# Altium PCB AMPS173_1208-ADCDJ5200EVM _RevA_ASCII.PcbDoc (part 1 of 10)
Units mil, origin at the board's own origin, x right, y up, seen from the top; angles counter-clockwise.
Board outline 10500 x 2750 mil, 14 copper layers (Top Copper, Layer 2 (GND1), Layer 3 (SIG1), Layer 4 (GND2, Layer 5 (PWR1), Layer 6 (GND3), Layer 7 (PWR/SIGNAL2), Layer 8 (PWR/SIGNAL3), Layer 9 (GND4), Layer 10 PWR2), Layer 11 (GND5), Layer 12 (SIG4), Layer 13 (GND6), Bottom Copper), stack 60.6 mil thick; 701 components, 826 nets, 3386 pads, 2128 vias.
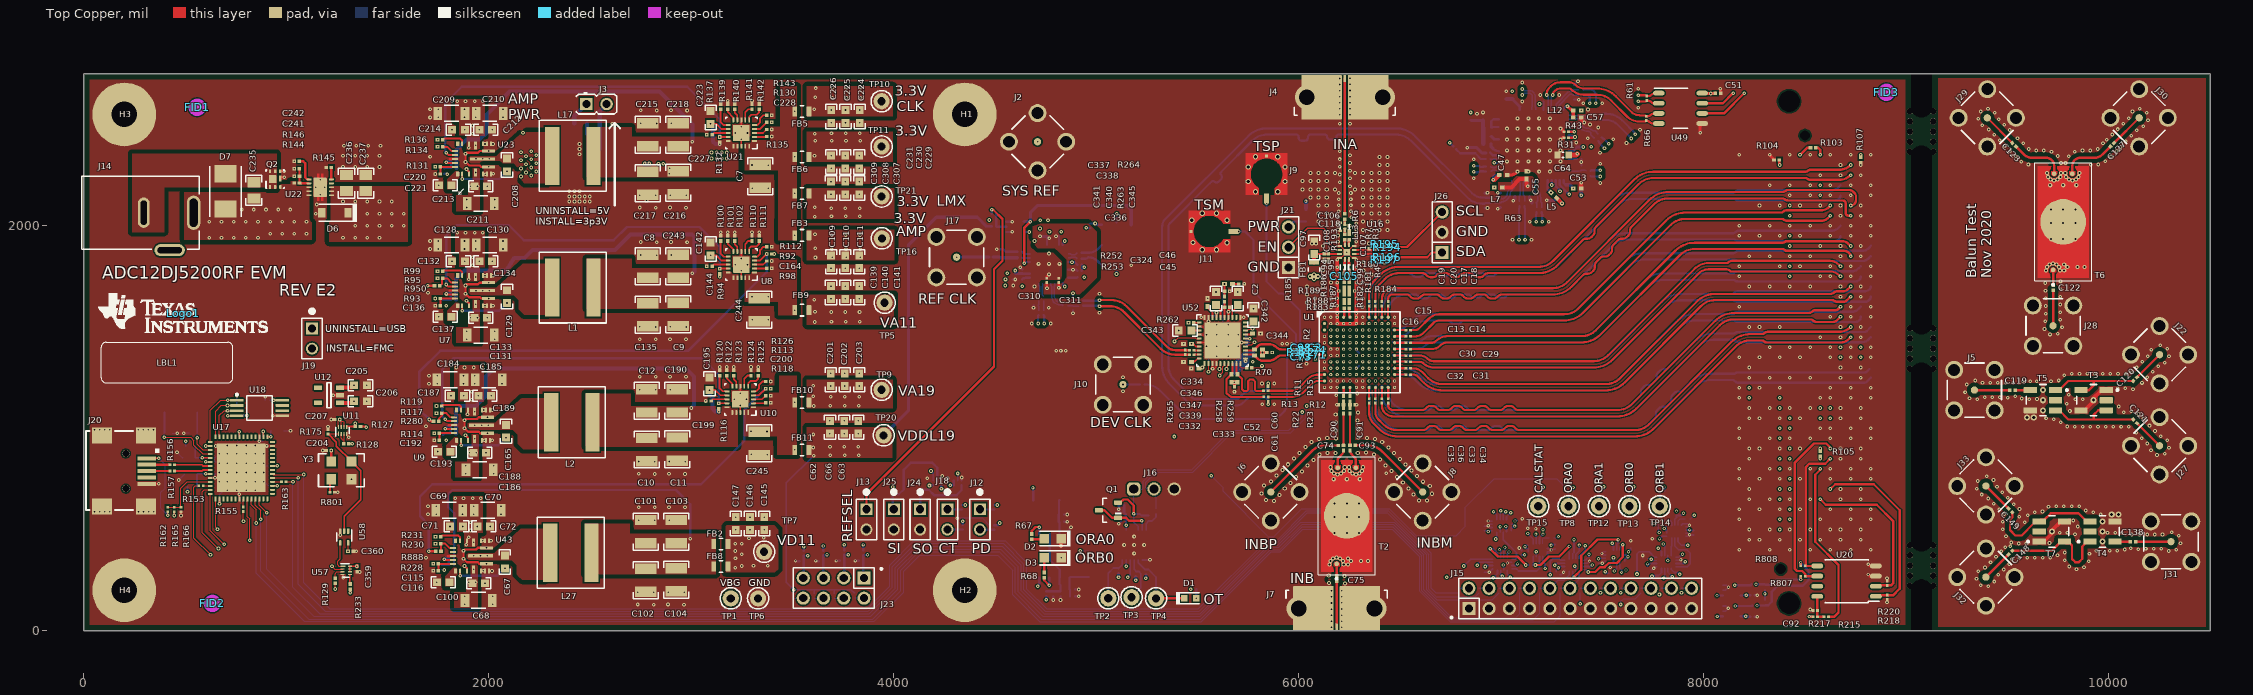
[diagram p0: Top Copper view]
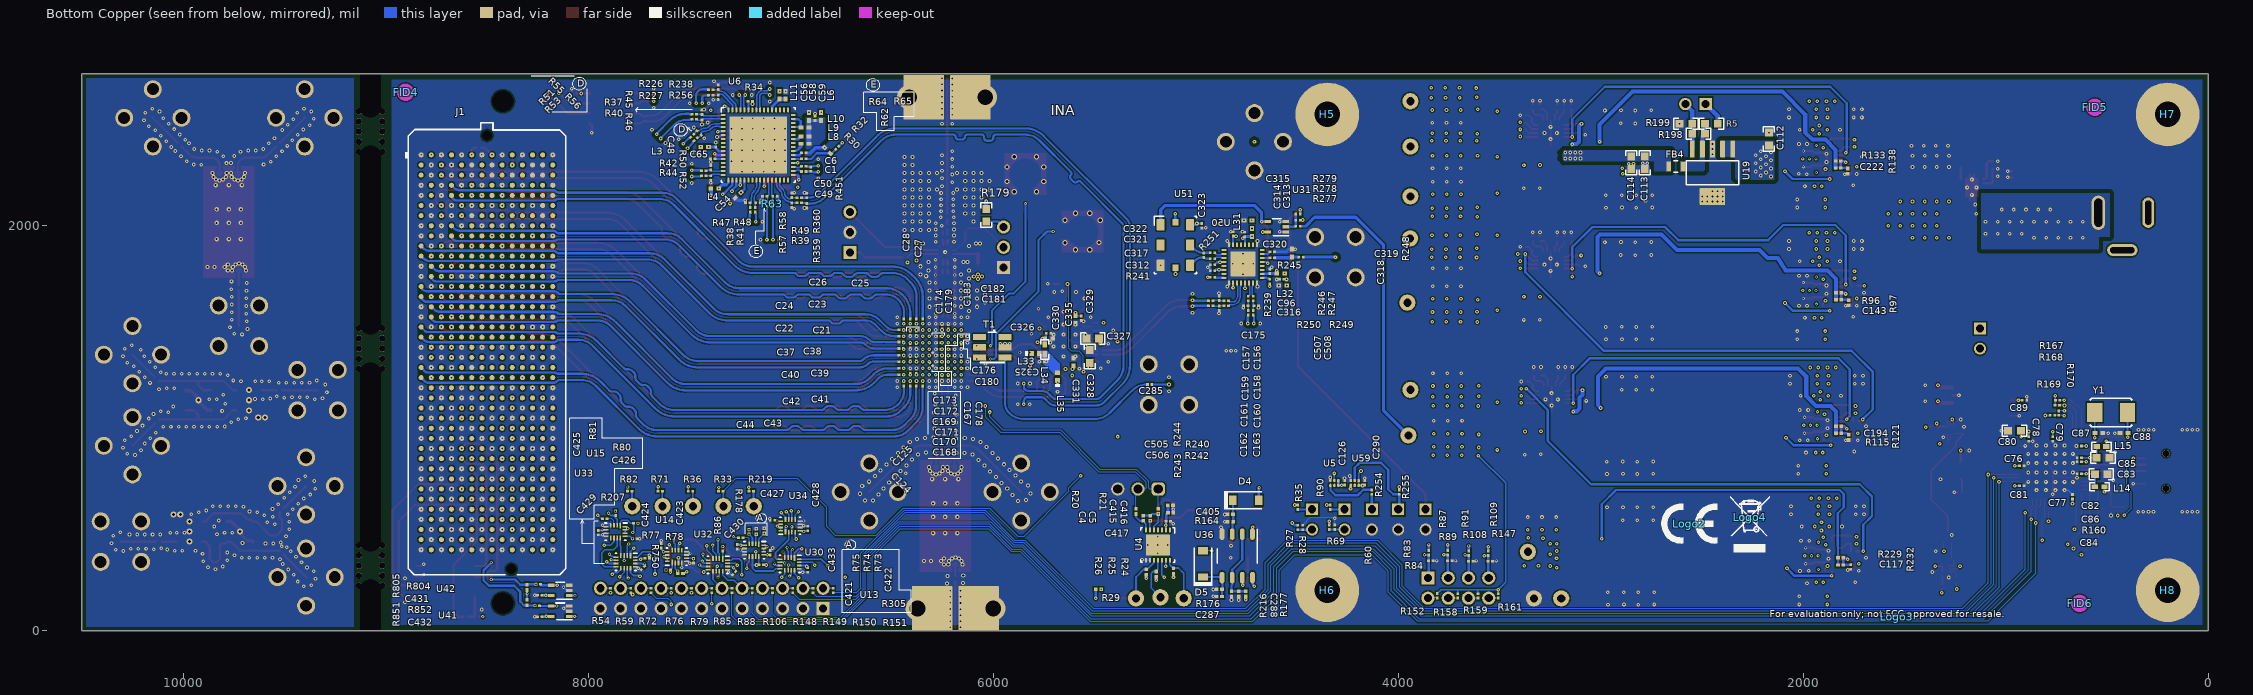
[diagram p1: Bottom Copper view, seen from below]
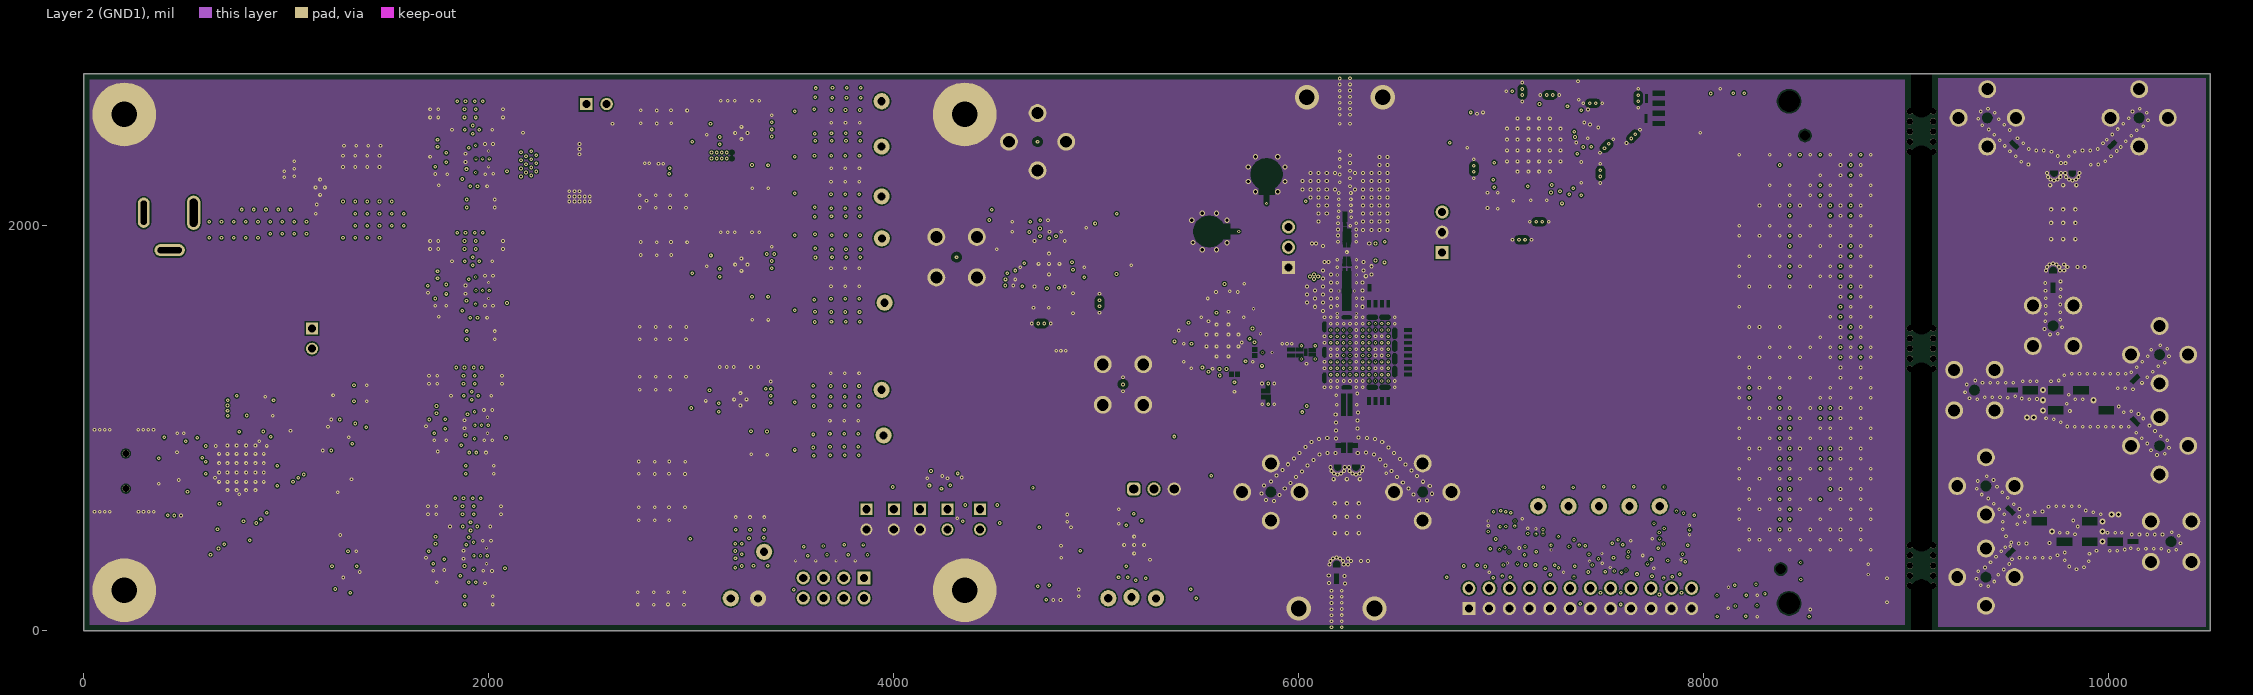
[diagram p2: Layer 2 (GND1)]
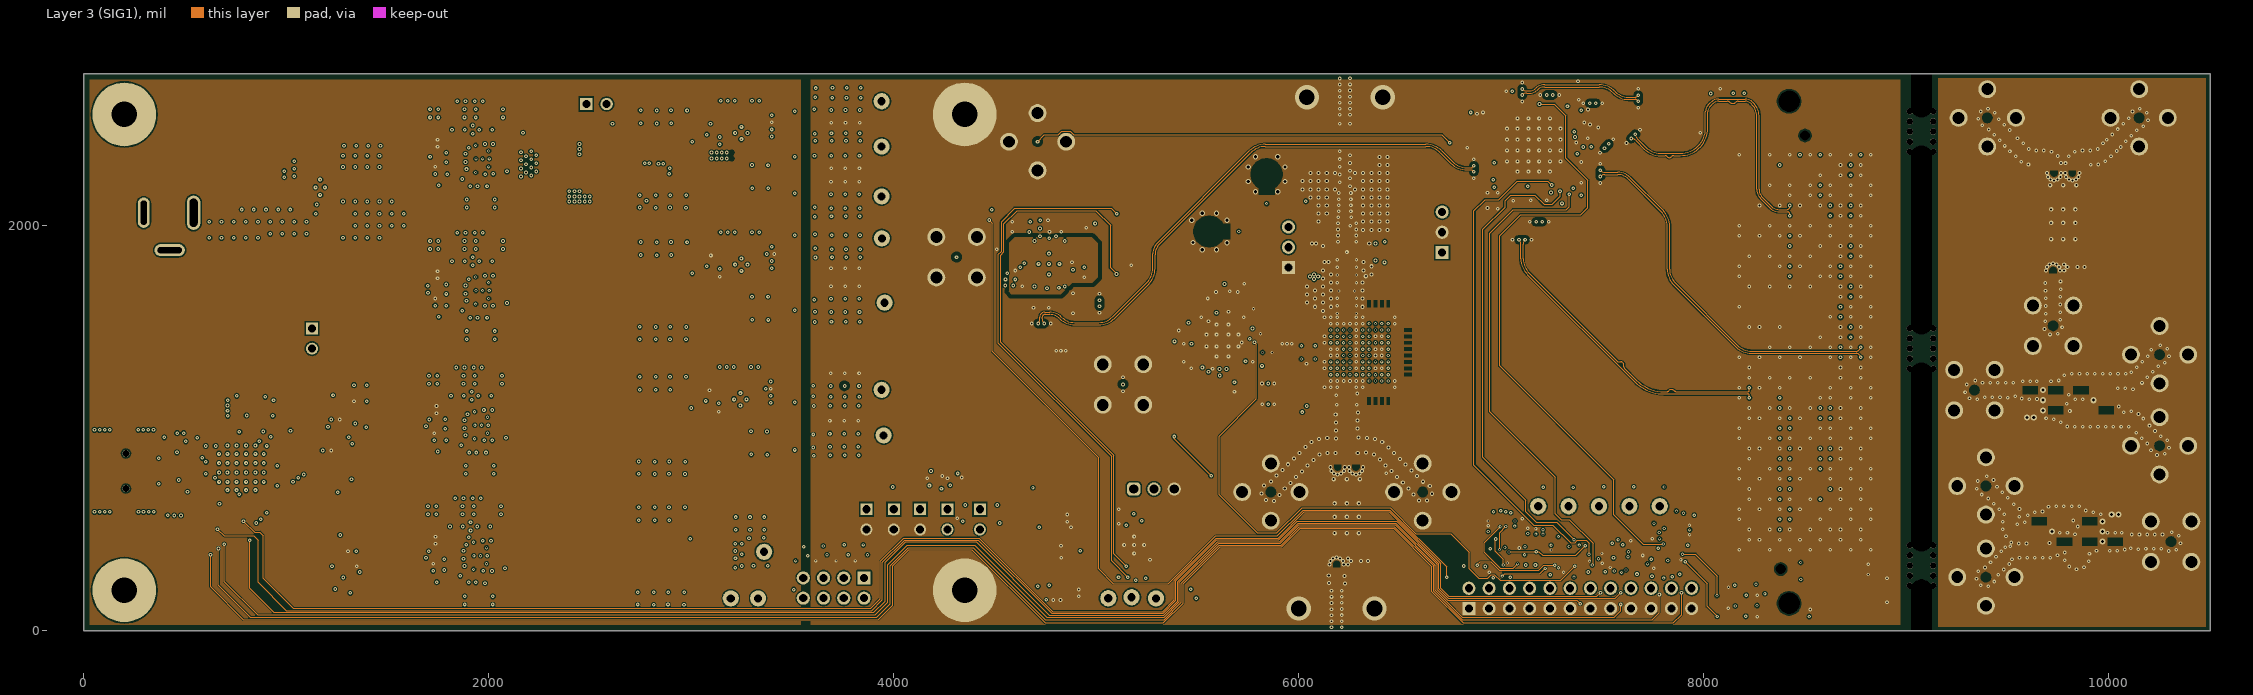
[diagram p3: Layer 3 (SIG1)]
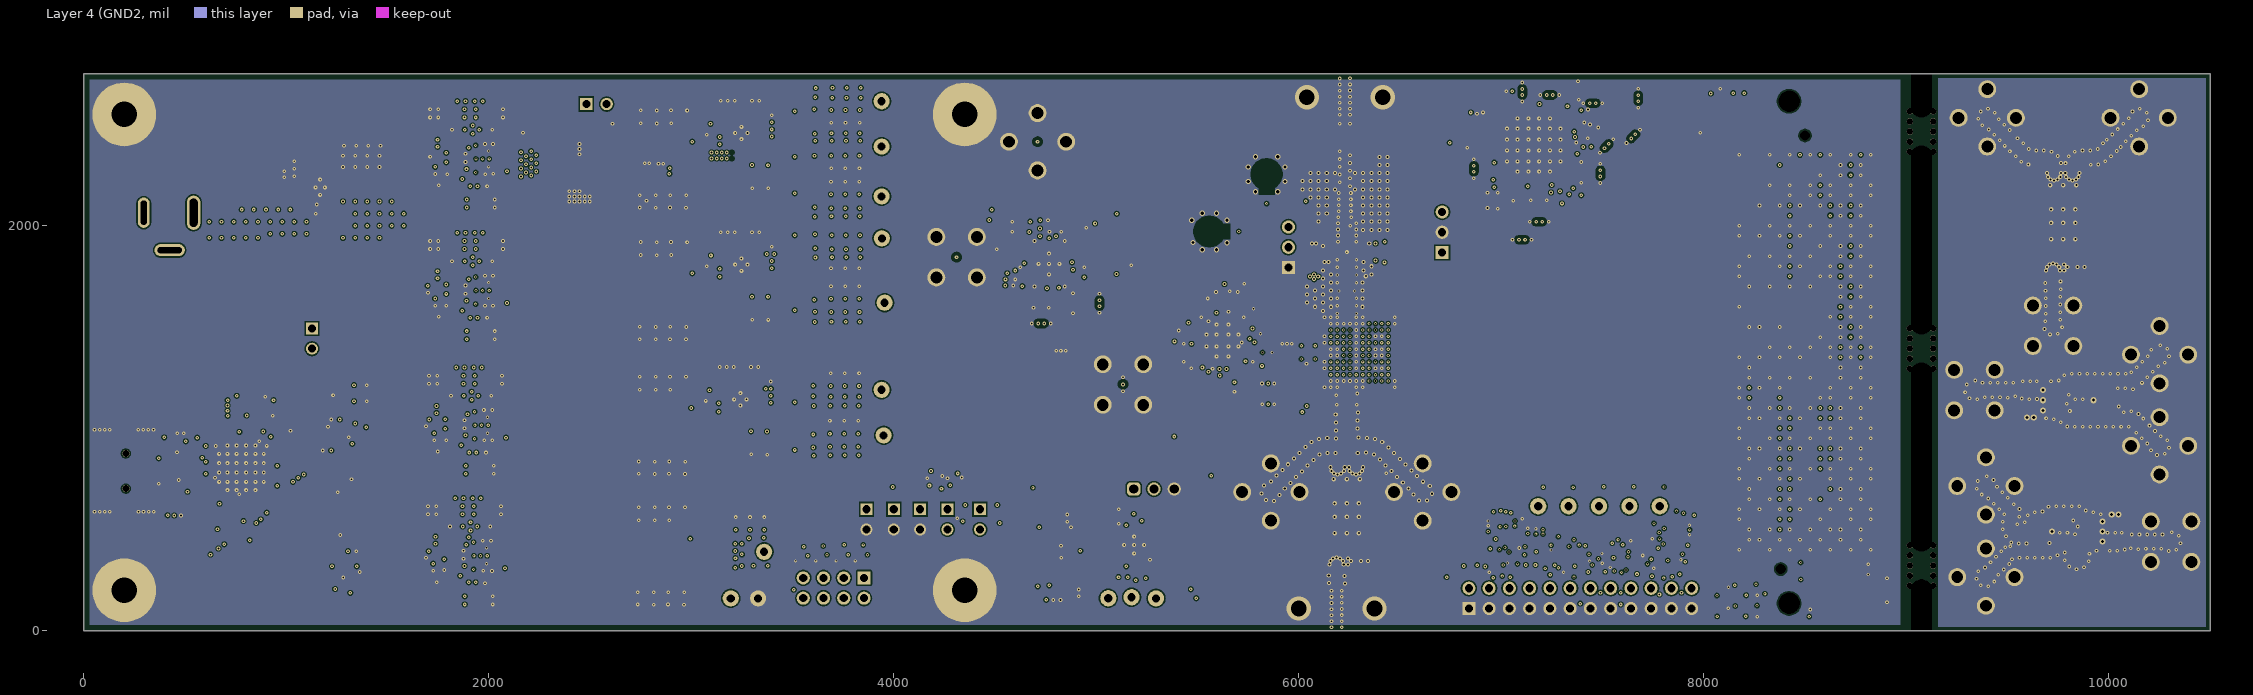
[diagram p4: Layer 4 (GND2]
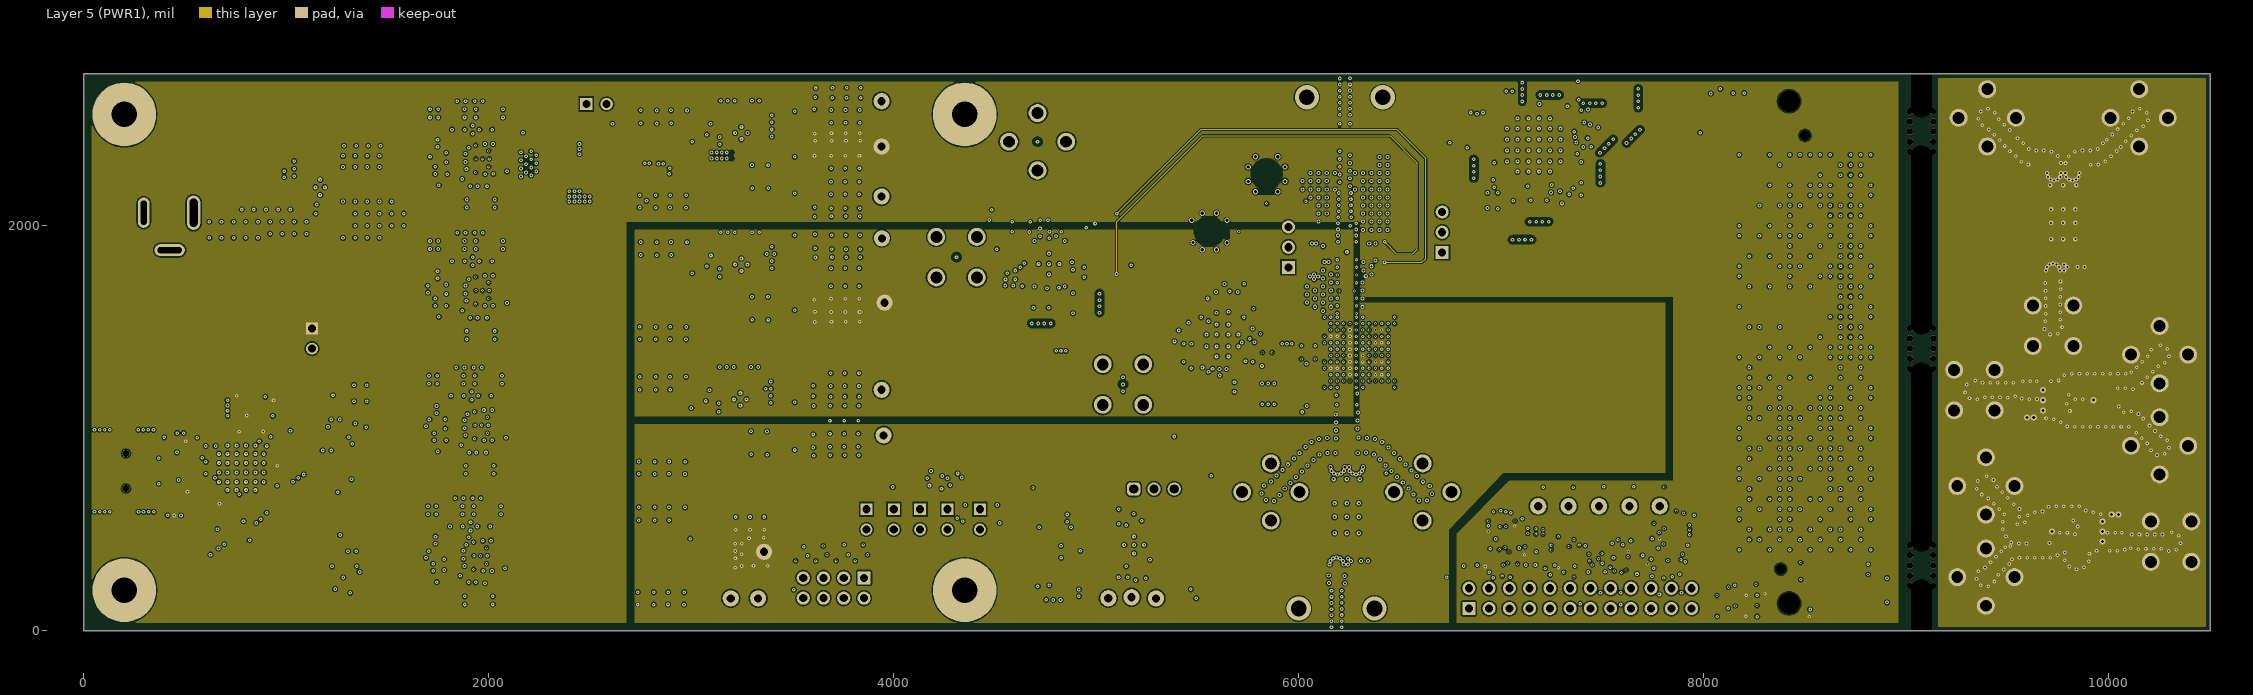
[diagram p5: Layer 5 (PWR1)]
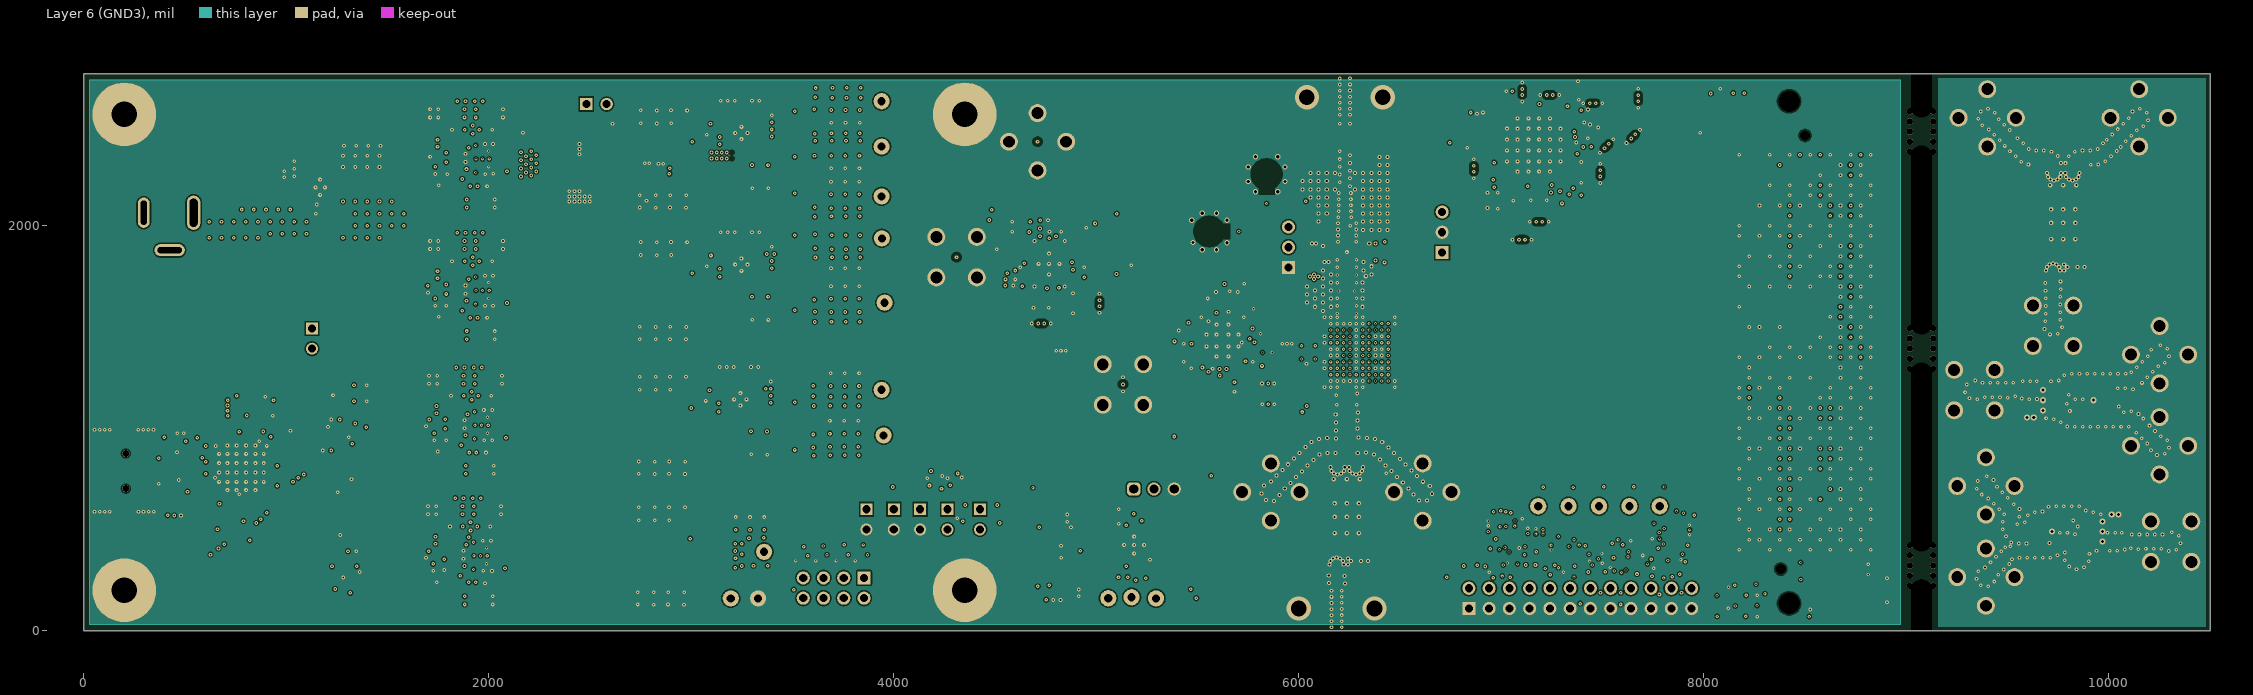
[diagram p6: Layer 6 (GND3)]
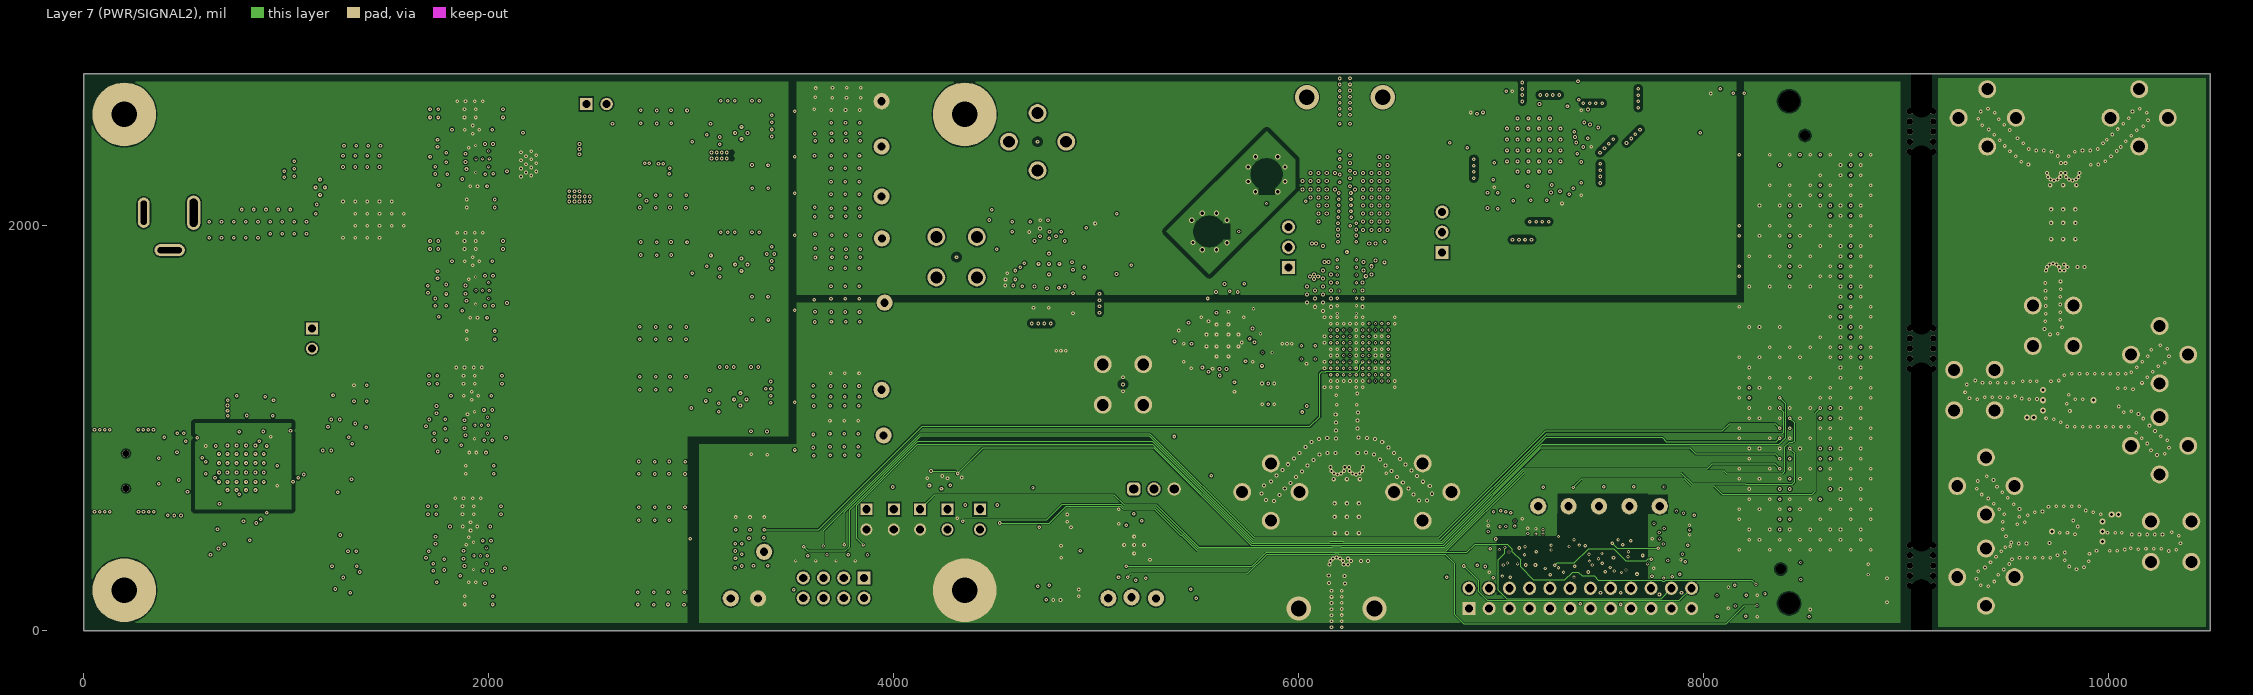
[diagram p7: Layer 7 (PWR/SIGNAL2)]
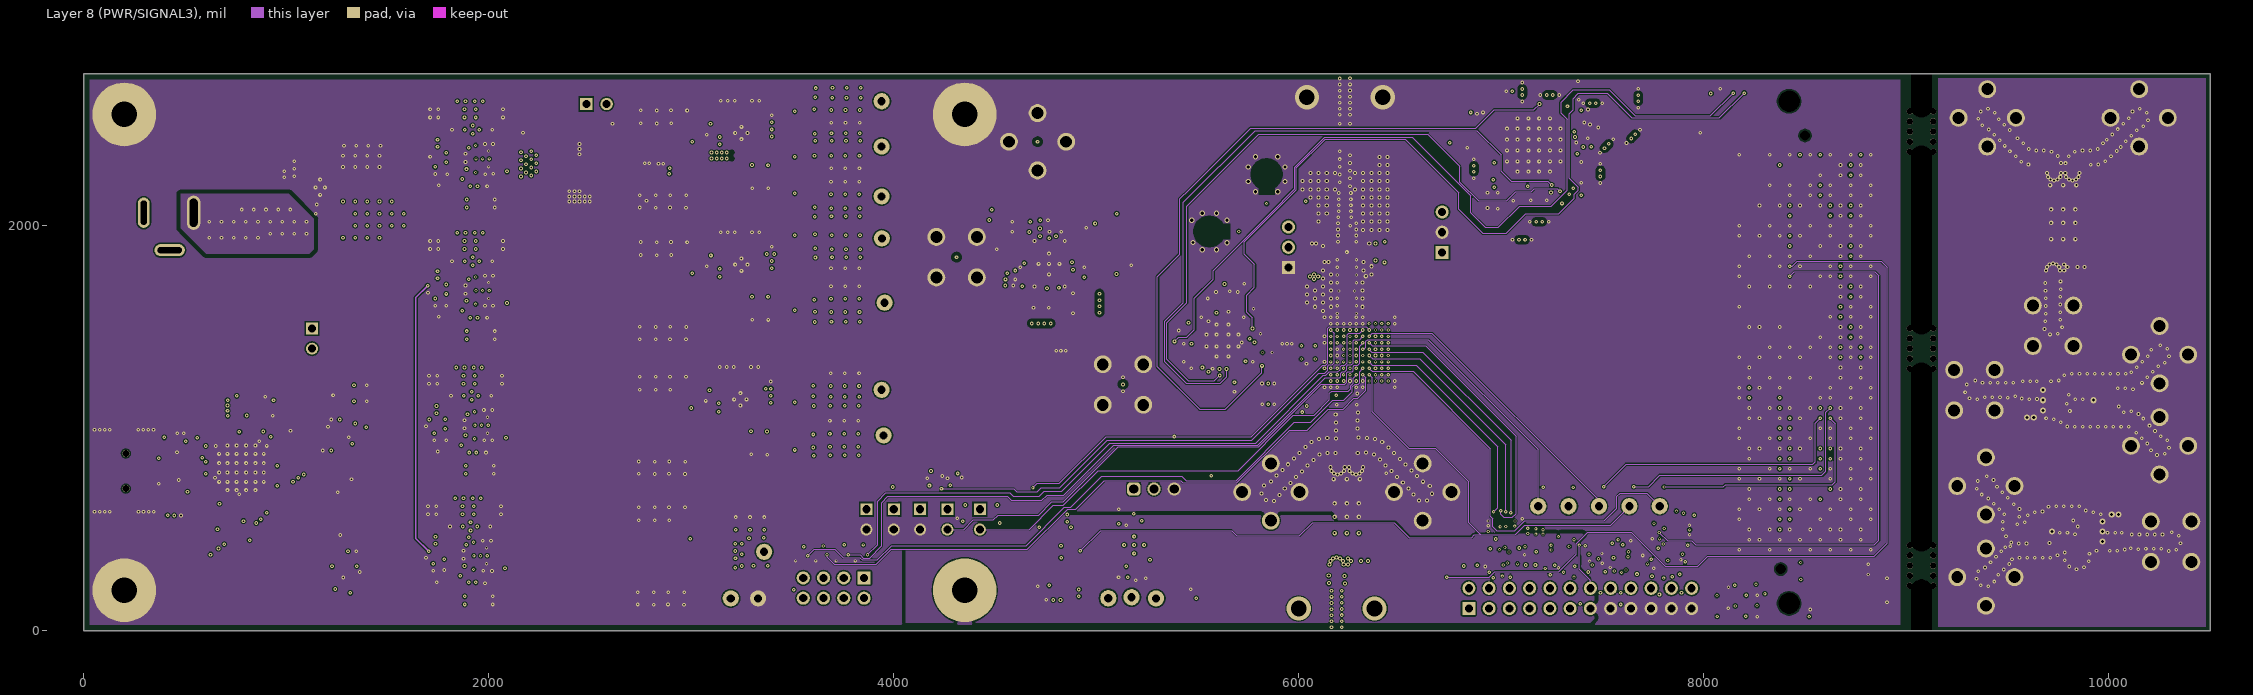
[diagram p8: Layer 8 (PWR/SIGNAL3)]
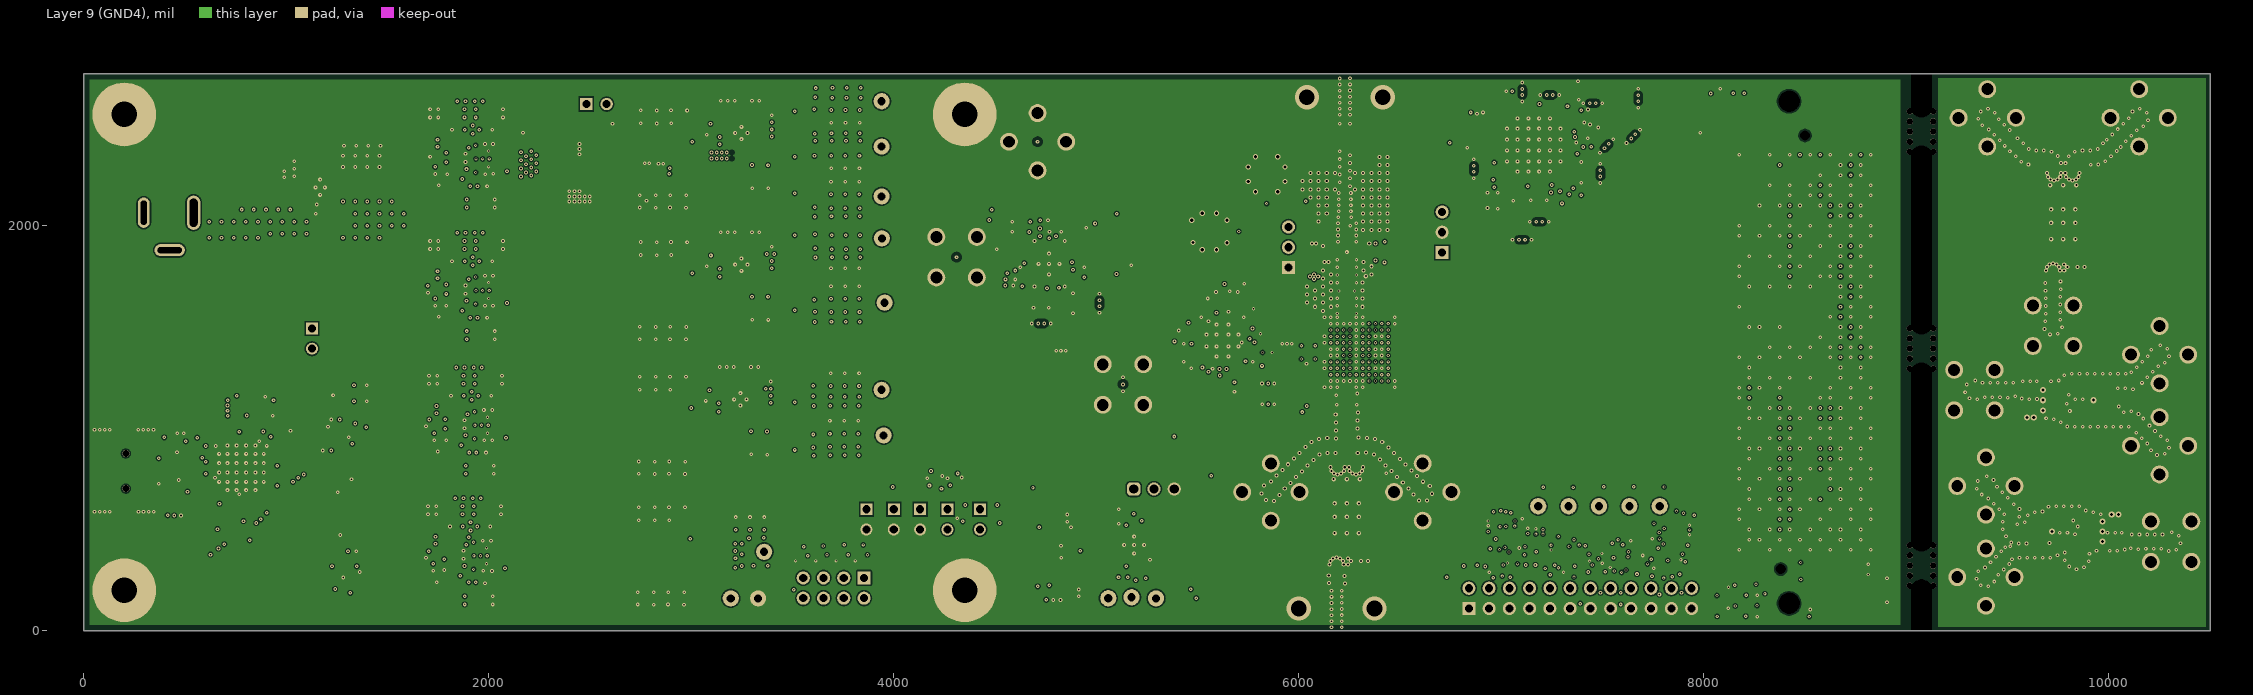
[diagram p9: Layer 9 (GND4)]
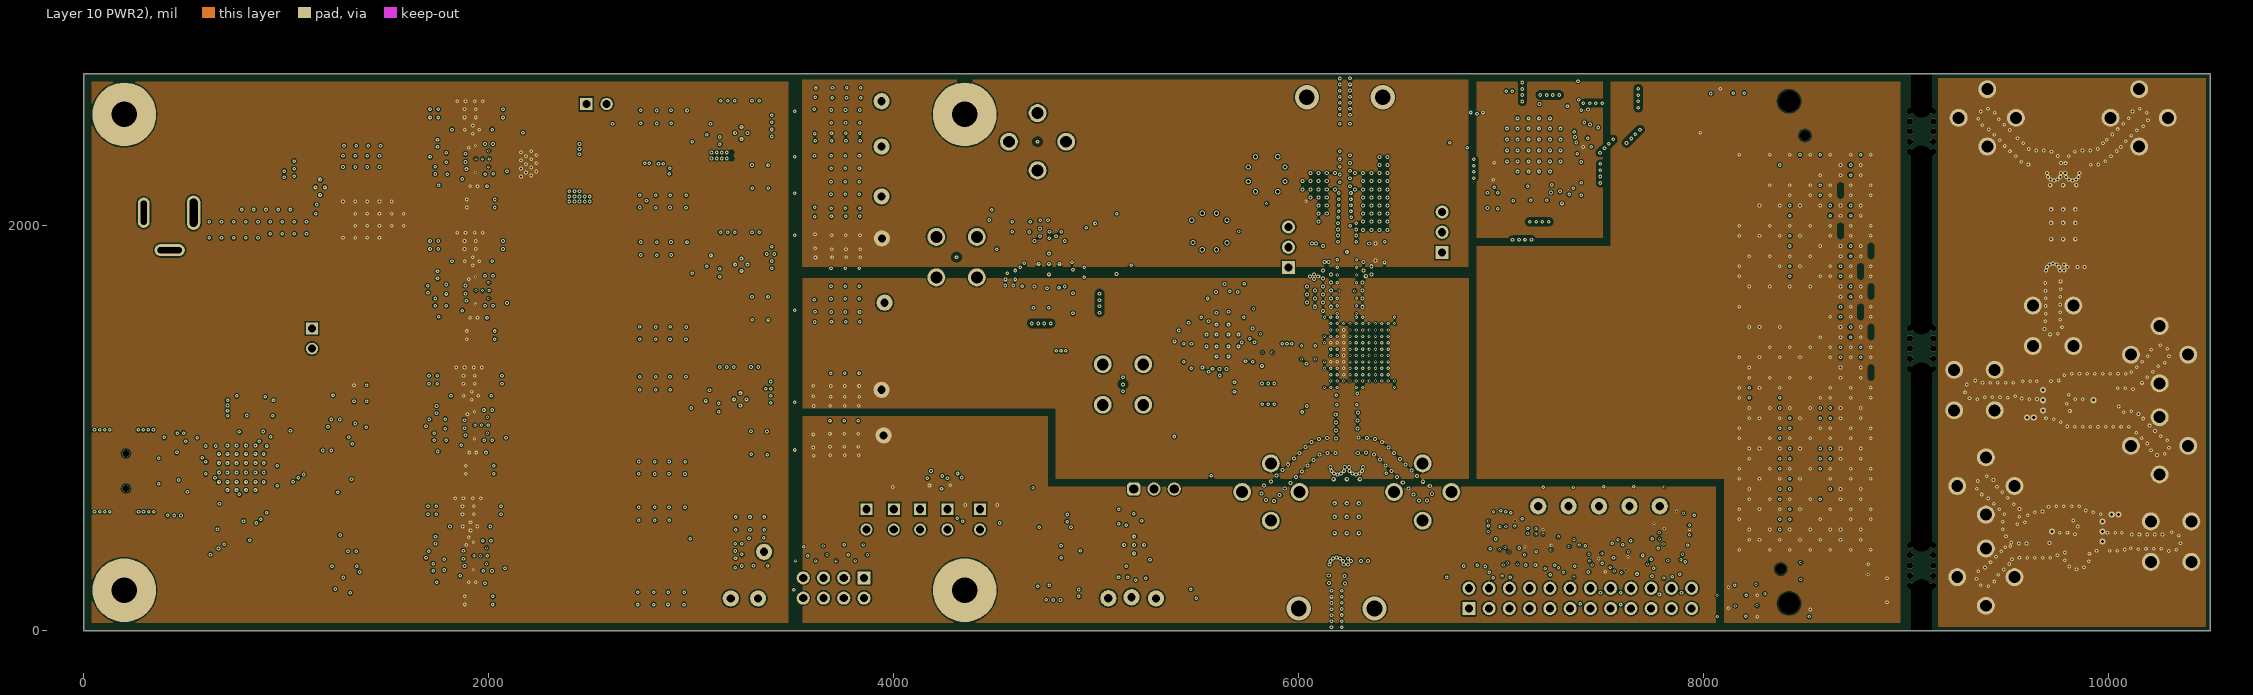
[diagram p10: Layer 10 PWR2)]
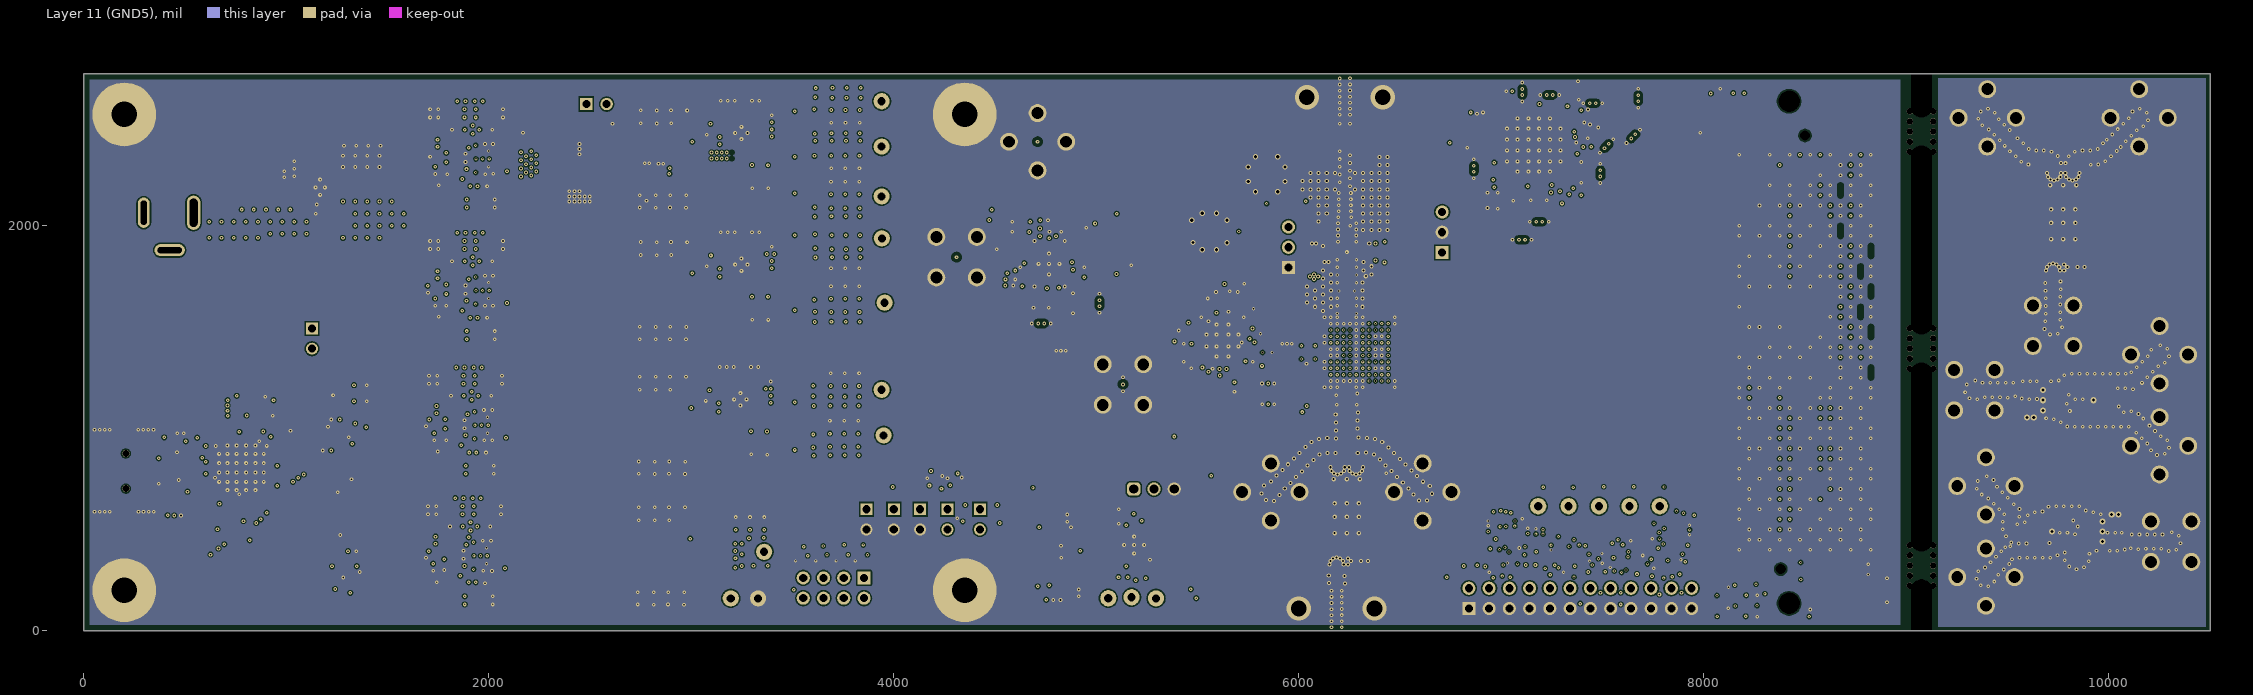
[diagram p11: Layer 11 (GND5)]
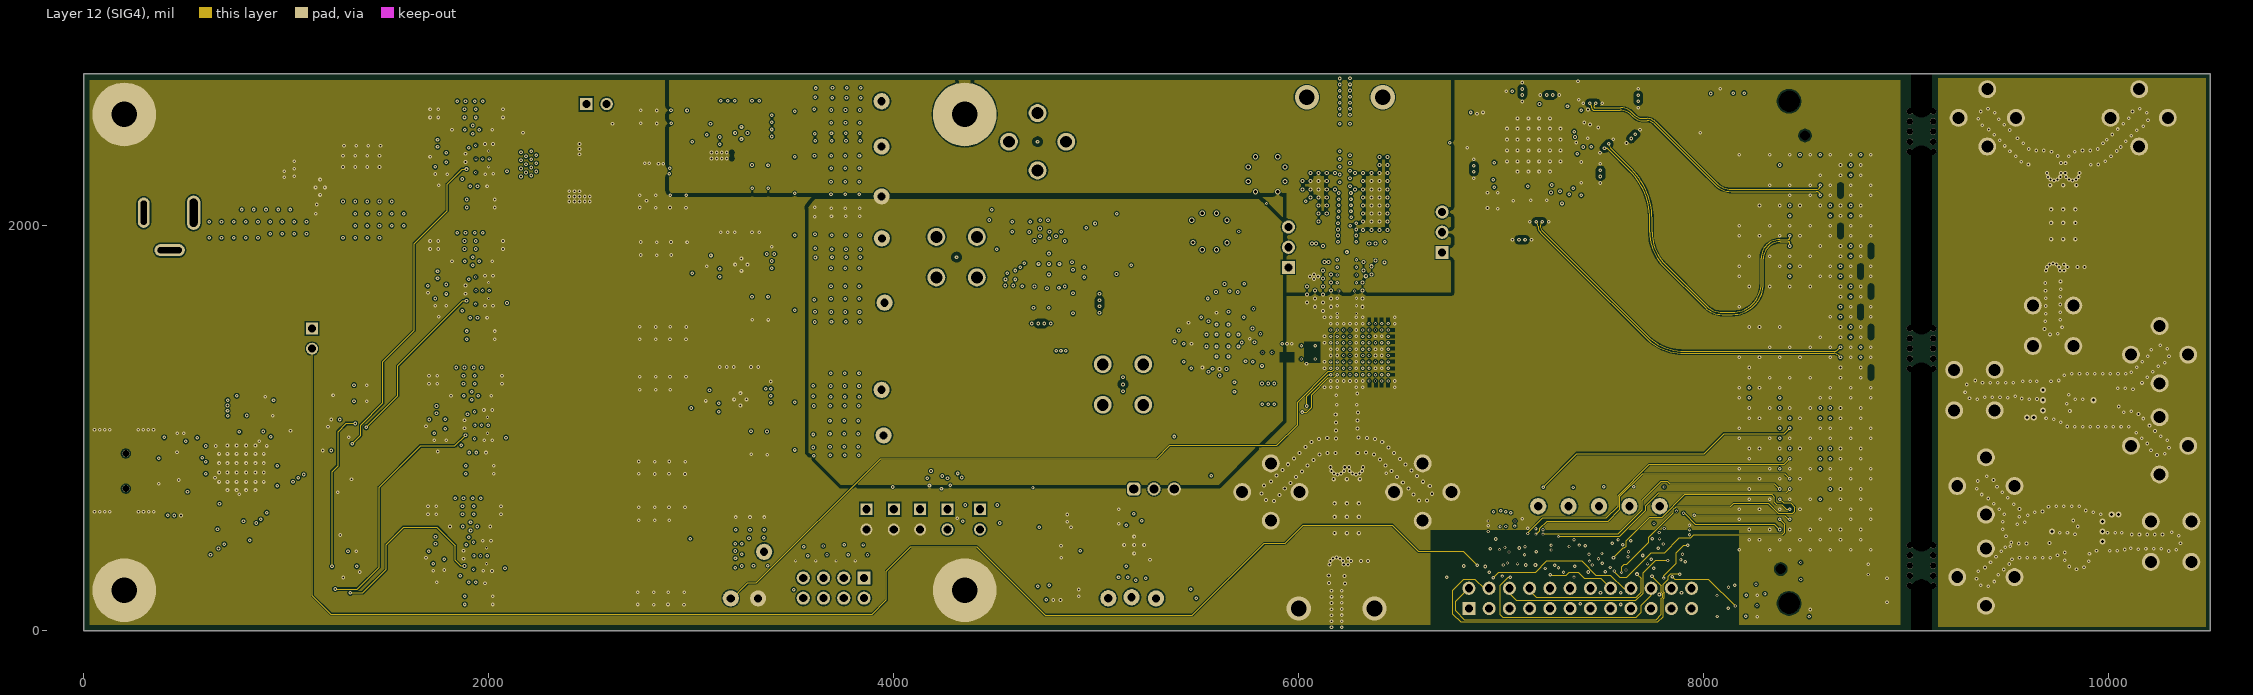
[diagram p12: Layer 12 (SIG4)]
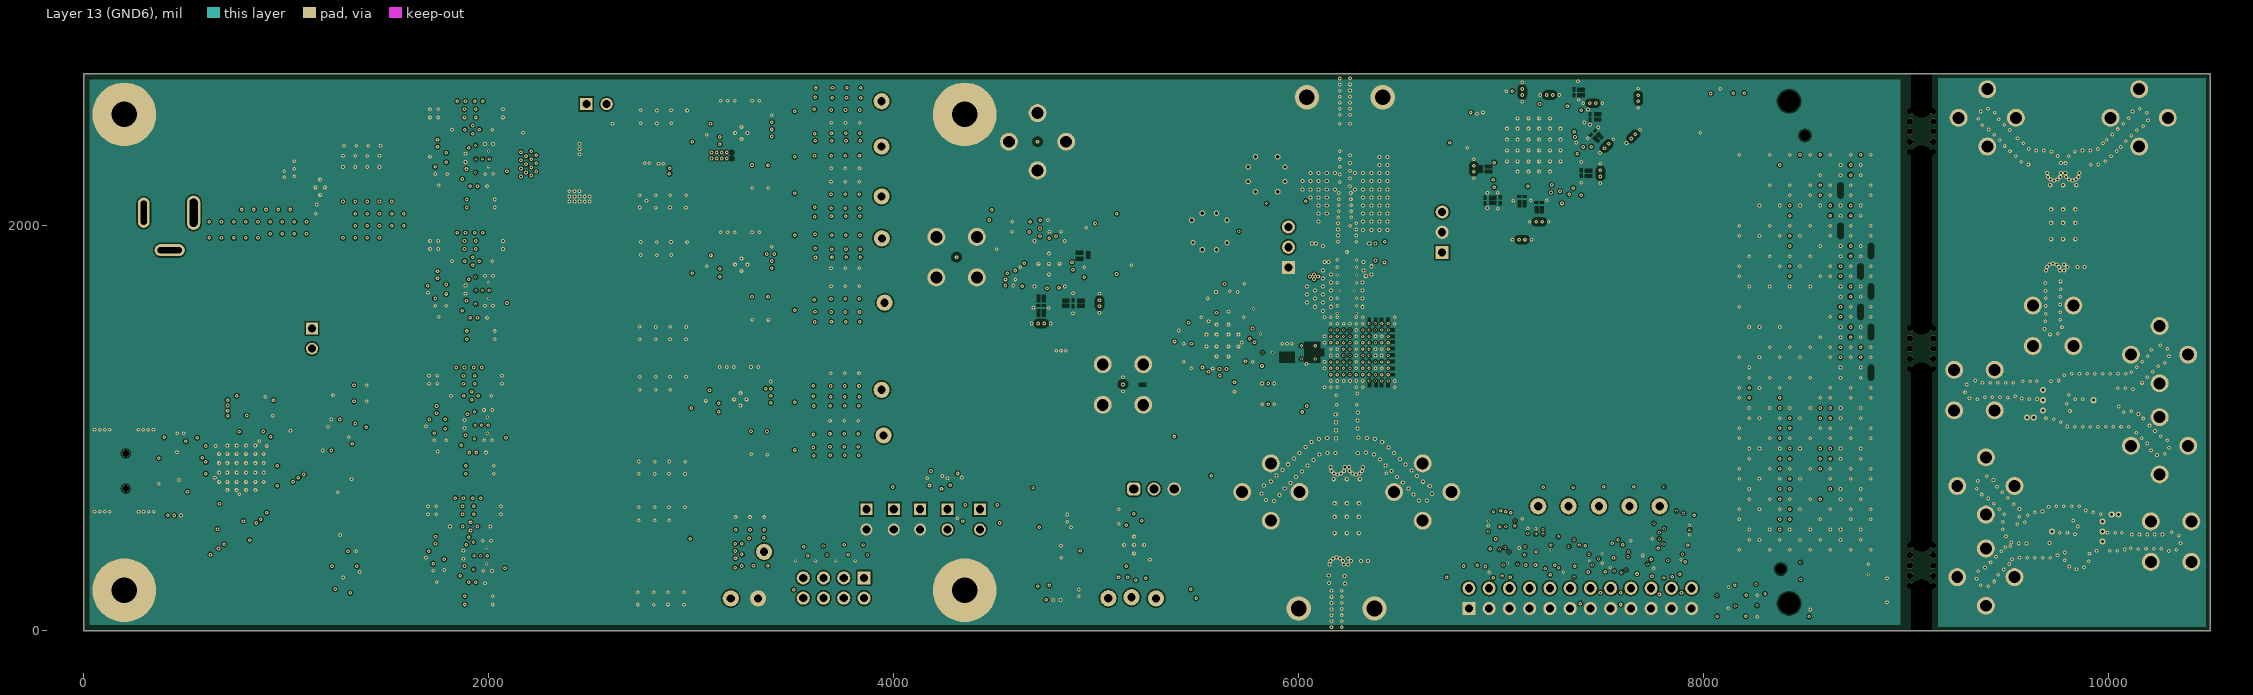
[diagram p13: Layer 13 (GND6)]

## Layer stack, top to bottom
Top Solder Mask: solder mask 0.5, TAIYO-4000-BN, Dk 3.9
Top Copper: signal copper 2
Dielectric 1: core 6, MEG6-R-5775K, Dk 3.42
Layer 2 (GND1): signal copper 0.6
Dielectric 2: prepreg 3.3, MEG6-R-5670K, Dk 3.23
Layer 3 (SIG1): signal copper 0.6
Dielectric 3: core 3, MEG6-R-5775K, Dk 3.42
Layer 4 (GND2: signal copper 0.6
Dielectric 4: prepreg 3.5, MEG6-R-5670K, Dk 3.23
Layer 5 (PWR1): signal copper 1.2
Dielectric 5: core 2.6, MEG6-R-5775K, Dk 3.58
Layer 6 (GND3): signal copper 1.2
Dielectric 6: prepreg 3, MEG6-R-5670K, Dk 3.23
Layer 7 (PWR/SIGNAL2): signal copper 1.2
Dielectric 7: core 3, MEG6-R-5775K, Dk 3.42
Layer 8 (PWR/SIGNAL3): signal copper 1.2
Dielectric 8: prepreg 3, MEG6-R-5670K, Dk 3.23
Layer 9 (GND4): signal copper 1.2
Dielectric 9: core 2.6, MEG6-R-5775K, Dk 3.58
Layer 10 PWR2): signal copper 1.2
Dielectric 10: prepreg 3.5, MEG6-R-5670K, Dk 3.23
Layer 11 (GND5): signal copper 0.6
Dielectric 11: core 3, MEG6-R-5775K, Dk 3.42
Layer 12 (SIG4): signal copper 0.6
Dielectric 12: prepreg 3.3, MEG6-R-5670K, Dk 3.23
Layer 13 (GND6): signal copper 0.6
Dielectric 13: core 6, MEG6-R-5775K, Dk 3.42
Bottom Copper: signal copper 2
Bottom Solder Mask: solder mask 0.5, TAIYO-4000-BN, Dk 3.9

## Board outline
0,0 0,2750 10500,2750 10500,0

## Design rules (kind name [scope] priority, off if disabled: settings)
AcuteAngle [All] p1: minimum=1.00000000000000E+0001 checktracksonly=FALSE
AssemblyTestPointUsage [All] p1: valid=2
BoardOutlineClearance [All] p1: gap=20 ignorepadtopadclearanceinfootprint=FALSE except(0: Arc-SplitContinuation Track-SplitContinuation SMDPad-SplitContinuation THPad-SplitContinuation Via-SplitContinuation Fill-SplitContinuation Poly-SplitContinuation Region-SplitContinuation Text-SplitContinuation)
Clearance Clearance_FID [InComponentClass('FiducialMark')] p1: gap=0 ignorepadtopadclearanceinfootprint=FALSE
Clearance serdes_1 [InNetClass('serdes')] p2: gap=5 ignorepadtopadclearanceinfootprint=FALSE except(0: Arc-Hole Track-Hole SMDPad-Hole THPad-Hole Via-Hole Fill-Hole Poly-Hole Region-Hole Text-Hole; 4.75: Arc-SMDPad Track-SMDPad; 36: Arc-Poly Track-Poly)
Clearance [All] p3: gap=5 ignorepadtopadclearanceinfootprint=FALSE except(0: Arc-Hole Track-Hole SMDPad-Hole THPad-Hole Via-Hole Fill-Hole Poly-Hole Region-Hole Text-Hole; 6: Arc-Poly Track-Poly; 7: SMDPad-Poly THPad-Poly; 20: Poly-Poly)
ComponentClearance ComponentClearance_MountingHoles_FiducialMarks [InComponentClass('Mounting Holes') vs InComponentClass('FiducialMark')] p1: gap=0 collisioncheckmode=3 verticalgap=0 showdistances=FALSE
ComponentClearance ComponentClearance_Shunt [InComponentClass('Header') vs InComponentClass('Shunt')] p2: gap=0 collisioncheckmode=3 verticalgap=0 showdistances=FALSE
ComponentClearance ComponentClearance_Logo [InComponentClass('Logo')] p3: gap=0 collisioncheckmode=3 verticalgap=0 showdistances=FALSE
ComponentClearance ComponentClearance_ScrewToNut [(HasFootprint('NY PMS 440 0025 PH')) vs (HasFootprint('Keystone_1902C'))] p4: gap=0 collisioncheckmode=3 verticalgap=0 showdistances=FALSE
ComponentClearance ComponentClearance_MountingHoles [InComponentClass('Mounting Holes')] p5: gap=0 collisioncheckmode=3 verticalgap=100000 showdistances=FALSE
ComponentClearance ComponentClearance_SmallPassives [HasFootprint('0201*') or HasFootprint('0402*') or HasFootprint('0508') or HasFootprint('0603*') or HasFootprint('0612') or HasFootprint('0805*') or HasFootprint('0815*') or HasFootprint('0830*') or HasFootprint('1206*') or HasFootprint('1210*') or HasFootprint('1808*') or HasFootprint('1812*') or HasFootprint('1825*') or HasFootprint('2010*') or HasFootprint('2220*') or HasFootprint('2225*') or HasFootprint('2512*') or HasFootprint('2728*') or HasFootprint('3518*') vs HasFootprint('0201*') or HasFootprint('0402*') or HasFootprint('0508') or HasFootprint('0603*') or HasFootprint('0612') or HasFootprint('0805*') or HasFootprint('0815*') or HasFootprint('0830*') or HasFootprint('1206*') or HasFootprint('1210*') or HasFootprint('1808*') or HasFootprint('1812*') or HasFootprint('1825*') or HasFootprint('2010*') or HasFootprint('2220*') or HasFootprint('2225*') or HasFootprint('2512*') or HasFootprint('2728*') or HasFootprint('3518*')] p6: gap=0 collisioncheckmode=3 verticalgap=0 showdistances=FALSE
ComponentClearance ComponentClearance_THtoSMT [IsThruComponent vs IsSMTComponent] p7: gap=0 collisioncheckmode=3 verticalgap=0 showdistances=FALSE
ComponentClearance ComponentClearance_THtoTH [IsThruComponent vs IsThruComponent] p8: gap=0 collisioncheckmode=3 verticalgap=0 showdistances=FALSE
ComponentClearance [All] p9: gap=0 collisioncheckmode=3 verticalgap=0 showdistances=FALSE
DiffPairsRouting 100OHM_TIGHT [InDifferentialPairClass('100OHM_TIGHT')] p1: maxlimit=20.5 minlimit=7 mostfreqgap=7 toplayer_maxgap=7 toplayer_minwidth=7 toplayer_maxwidth=11.5 toplayer_prefwidth=7 midlayer1_maxgap=7 midlayer1_minwidth=7 midlayer1_maxwidth=7 midlayer1_prefwidth=7 midlayer2_maxgap=7 midlayer2_minwidth=7 midlayer2_maxwidth=7 midlayer2_prefwidth=7 midlayer3_maxgap=7 midlayer3_minwidth=7 midlayer3_maxwidth=7 midlayer3_prefwidth=7 midlayer4_maxgap=7 midlayer4_minwidth=7 midlayer4_maxwidth=7 midlayer4_prefwidth=7 midlayer5_maxgap=7 midlayer5_minwidth=7 midlayer5_maxwidth=7 midlayer5_prefwidth=7 midlayer6_maxgap=7 midlayer6_minwidth=7 midlayer6_maxwidth=7 midlayer6_prefwidth=7 midlayer7_maxgap=7 midlayer7_minwidth=7 midlayer7_maxwidth=7 midlayer7_prefwidth=7 midlayer8_maxgap=7 midlayer8_minwidth=7 midlayer8_maxwidth=7 midlayer8_prefwidth=7 midlayer9_maxgap=7 midlayer9_minwidth=7 midlayer9_maxwidth=7 midlayer9_prefwidth=7 midlayer10_maxgap=7 midlayer10_minwidth=7 midlayer10_maxwidth=7 midlayer10_prefwidth=7 midlayer11_maxgap=7 midlayer11_minwidth=7 midlayer11_maxwidth=7 midlayer11_prefwidth=7 midlayer12_maxgap=7 midlayer12_minwidth=7 midlayer12_maxwidth=7 midlayer12_prefwidth=7 bottomlayer_minwidth=7 bottomlayer_maxwidth=20.5 bottomlayer_prefwidth=7 maxuncoupledlength=500
DiffPairsRouting 100OHM_TIGHT_1 [All] p2: maxlimit=20.5 minlimit=7 mostfreqgap=7 toplayer_maxgap=7 toplayer_minwidth=7 toplayer_maxwidth=11.5 toplayer_prefwidth=7 midlayer1_maxgap=7 midlayer1_minwidth=7 midlayer1_maxwidth=7 midlayer1_prefwidth=7 midlayer2_maxgap=7 midlayer2_minwidth=7 midlayer2_maxwidth=7 midlayer2_prefwidth=7 midlayer3_maxgap=7 midlayer3_minwidth=7 midlayer3_maxwidth=7 midlayer3_prefwidth=7 midlayer4_maxgap=7 midlayer4_minwidth=7 midlayer4_maxwidth=7 midlayer4_prefwidth=7 midlayer5_maxgap=7 midlayer5_minwidth=7 midlayer5_maxwidth=7 midlayer5_prefwidth=7 midlayer6_maxgap=7 midlayer6_minwidth=7 midlayer6_maxwidth=7 midlayer6_prefwidth=7 midlayer7_maxgap=7 midlayer7_minwidth=7 midlayer7_maxwidth=7 midlayer7_prefwidth=7 midlayer8_maxgap=7 midlayer8_minwidth=7 midlayer8_maxwidth=7 midlayer8_prefwidth=7 midlayer9_maxgap=7 midlayer9_minwidth=7 midlayer9_maxwidth=7 midlayer9_prefwidth=7 midlayer10_maxgap=7 midlayer10_minwidth=7 midlayer10_maxwidth=7 midlayer10_prefwidth=7 midlayer11_maxgap=7 midlayer11_minwidth=7 midlayer11_maxwidth=7 midlayer11_prefwidth=7 midlayer12_maxgap=7 midlayer12_minwidth=7 midlayer12_maxwidth=7 midlayer12_prefwidth=7 bottomlayer_minwidth=7 bottomlayer_maxwidth=20.5 bottomlayer_prefwidth=7 maxuncoupledlength=500
DiffPairsRouting SERDES [InNetClass('SERDES')] p3: maxlimit=20.5 minlimit=8 mostfreqgap=20.5 toplayer_mingap=20.5 toplayer_minwidth=10.5 toplayer_maxwidth=11.5 toplayer_prefwidth=10.5 midlayer1_mingap=20.5 midlayer1_minwidth=10.5 midlayer1_maxwidth=10.5 midlayer1_prefwidth=10.5 midlayer2_mingap=20.5 midlayer2_minwidth=10.5 midlayer2_maxwidth=10.5 midlayer2_prefwidth=10.5 midlayer3_maxgap=8 midlayer3_prefgap=8 midlayer3_minwidth=3.25 midlayer3_maxwidth=3.25 midlayer3_prefwidth=3.25 midlayer4_mingap=20.5 midlayer4_minwidth=10.5 midlayer4_maxwidth=10.5 midlayer4_prefwidth=10.5 midlayer5_mingap=20.5 midlayer5_minwidth=10.5 midlayer5_maxwidth=10.5 midlayer5_prefwidth=10.5 midlayer6_mingap=20.5 midlayer6_minwidth=10.5 midlayer6_maxwidth=10.5 midlayer6_prefwidth=10.5 midlayer7_mingap=20.5 midlayer7_minwidth=10.5 midlayer7_maxwidth=10.5 midlayer7_prefwidth=10.5 midlayer8_mingap=20.5 midlayer8_minwidth=10.5 midlayer8_maxwidth=10.5 midlayer8_prefwidth=10.5 midlayer9_mingap=20.5 midlayer9_minwidth=10.5 midlayer9_maxwidth=10.5 midlayer9_prefwidth=10.5 midlayer10_mingap=20.5 midlayer10_minwidth=10.5 midlayer10_maxwidth=10.5 midlayer10_prefwidth=10.5 midlayer11_maxgap=8 midlayer11_prefgap=8 midlayer11_minwidth=3.25 midlayer11_maxwidth=3.25 midlayer11_prefwidth=3.25 midlayer12_mingap=20.5 midlayer12_minwidth=10.5 midlayer12_maxwidth=10.5 midlayer12_prefwidth=10.5 bottomlayer_mingap=20.5 bottomlayer_minwidth=10.5 bottomlayer_maxwidth=11.5 bottomlayer_prefwidth=10.5 maxuncoupledlength=500
DiffPairsRouting sense [InDifferentialPairClass('sense')] p4: maxlimit=20.5 minlimit=6 mostfreqgap=6 toplayer_maxgap=6 toplayer_minwidth=6 toplayer_maxwidth=11.5 toplayer_prefwidth=6 midlayer1_maxgap=6 midlayer1_minwidth=6 midlayer1_maxwidth=6 midlayer1_prefwidth=6 midlayer2_maxgap=6 midlayer2_minwidth=6 midlayer2_maxwidth=6 midlayer2_prefwidth=6 midlayer3_maxgap=6 midlayer3_minwidth=6 midlayer3_maxwidth=6 midlayer3_prefwidth=6 midlayer4_maxgap=6 midlayer4_minwidth=6 midlayer4_maxwidth=6 midlayer4_prefwidth=6 midlayer5_maxgap=6 midlayer5_minwidth=6 midlayer5_maxwidth=6 midlayer5_prefwidth=6 midlayer6_maxgap=6 midlayer6_minwidth=6 midlayer6_maxwidth=6 midlayer6_prefwidth=6 midlayer7_maxgap=6 midlayer7_minwidth=6 midlayer7_maxwidth=6 midlayer7_prefwidth=6 midlayer8_maxgap=6 midlayer8_minwidth=6 midlayer8_maxwidth=6 midlayer8_prefwidth=6 midlayer9_maxgap=6 midlayer9_minwidth=6 midlayer9_maxwidth=6 midlayer9_prefwidth=6 midlayer10_maxgap=6 midlayer10_minwidth=6 midlayer10_maxwidth=6 midlayer10_prefwidth=6 midlayer11_maxgap=6 midlayer11_minwidth=6 midlayer11_maxwidth=6 midlayer11_prefwidth=6 midlayer12_maxgap=6 midlayer12_minwidth=6 midlayer12_maxwidth=6 midlayer12_prefwidth=6 bottomlayer_minwidth=6 bottomlayer_maxwidth=10.5 bottomlayer_prefwidth=6 maxuncoupledlength=500
FabricationTestPointUsage TestPointUsage [All] p1: valid=2 allowmultiple=FALSE
FabricationTestpoint Testpoint [All] p1: side=3 testpointundercomponent=TRUE minsize=40 maxsize=100 preferedsize=60 minholesize=0 maxholesize=40 preferedholesize=32 testpointgrid=1 allowsidetop=TRUE allowsidebottom=TRUE usegrid=TRUE gridtolerance=0.01
FanoutControl Fanout_LCC [IsLCC] p1: bgadir=Out bgaviamode=Centered fanoutstyle=Auto fanoutdirection=Alternating viagrid=1 // Fanout_LCC (Default Rule)
FanoutControl Fanout_BGA [IsBGA or WithinRoom('FMC') or WithinRoom('FMC2')] p2: bgadir=Out bgaviamode=Centered fanoutstyle=UnderPads fanoutdirection=Alternating viagrid=1 // Fanout_BGA (Default Rule)
FanoutControl Fanout_Default [All] p4: bgadir=Out bgaviamode=Centered fanoutstyle=Auto fanoutdirection=Alternating viagrid=1 // Fanout_Default (Default Rule)
FanoutControl Fanout_Small [(CompPinCount < 5)] p5: bgadir=Out bgaviamode=Centered fanoutstyle=Auto fanoutdirection=OutThenIn viagrid=1 // Fanout_Small (Default Rule)
HoleSize [All] p1: absolutevalues=TRUE maxlimit=251 minlimit=7.5 maxpercent=80.000 minpercent=20.000
HoleToHoleClearance [All] p1: gap=7 allowstackedmicrovias=TRUE
Length [InNet('SYSREF_ADC_LMK_N')] p1: maxlimit=3375 minlimit=3374
Length clksignal [InNetClass('clksignal')] p2: maxlimit=1738 minlimit=1728
Length All [All] p3 off: maxlimit=3913.56 minlimit=1
MatchedLengths xsignals1 [InxSignal('NetC149_2_PP2') or InxSignal('NetC148_2_PP1')] p1: tolerance=1 checknetsindiffpair=FALSE checkdiffpairvsdiffpair=TRUE checkxsignals=TRUE checkothers=TRUE
MatchedLengths xsignals1_1 [InxSignal('NetC149_2_PP1') or InxSignal('NetC148_2_PP2')] p2: tolerance=1 checknetsindiffpair=FALSE checkdiffpairvsdiffpair=TRUE checkxsignals=TRUE checkothers=TRUE
MatchedLengths [InDifferentialPairClass('100ohmdiff_tight')] p3: tolerance=1500 checknetsindiffpair=TRUE checkdiffpairvsdiffpair=FALSE checkxsignals=FALSE checkothers=FALSE
MaximumViaCount [All] p1: limit=5000
MinimumAnnularRing MinimumAnnularRing_ThermalPadVias [IsVia and InAnyComponent] p1: minimumring=3.5
MinimumAnnularRing [All] p2: minimumring=3.5
MinimumSolderMaskSliver MinimumSolderMaskSliver_Logo [InComponentClass('Logo') vs InComponentClass('Logo')] p1: minsoldermaskwidth=0
MinimumSolderMaskSliver [All] p2: minsoldermaskwidth=0
PlaneClearance PlaneClearance_BGA [WithinRoom('BGA') or WithinRoom('BGA2')] p1: clearance=4
PlaneClearance [All] p2: clearance=5
PlaneConnect [All] p1: planeconnectstyle=Direct reliefexpansion=9.84 reliefentries=4 reliefconductorwidth=9.84 reliefairgap=9.84
PolygonConnect [All] p1: connectstyle=Direct reliefconductorwidth=15 reliefentries=4 polygonreliefangle="90 Angle" airgapwidth=8
RoomDefinition GPIO_RevE2 [InComponentClass('GPIO_RevE2')] p1 off: confinementstyle=ConfineIn formatcopy=TRUE lockcomponents=FALSE outline 8102.06,267.64 8102.06,2516.94 8910.51,2516.94 8910.51,267.64
RoomDefinition BGA [InComponent('U1')] p2 off: confinementstyle=ConfineIn formatcopy=TRUE lockcomponents=FALSE outline 6082.4,1166.26 6082.4,1583.74 6508.74,1583.74 6508.74,1166.26
RoutingCorners RoutingCorners_1 [InNetClass('SERDES')] p1: cornerstyle=Round minsetback=100 maxsetback=1000
RoutingCorners [All] p2: cornerstyle=45-Degree minsetback=1000 maxsetback=1000
RoutingVias [All] p1: holewidth=8 width=16 viastyle="Through Hole" minholewidth=6 minwidth=15.75 maxholewidth=40 maxwidth=50
SilkToBoardRegionClearance [Not ((IsComment or IsDesignator) And (Hide <> 'False')) and not InRegion(1000,500,4000,800)] p1:
SilkToSilkClearance SilkToSilkClearance_Pb-FreeLogo [(HasFootprint('Pb-Free_Overlay_Medium') OR HasFootprint('Pb-Free_Overlay_Small')) vs (HasFootprint('Pb-Free_Overlay_Medium') OR HasFootprint('Pb-Free_Overlay_Small'))] p1: silktosilkclearance=0
SilkToSilkClearance [All] p2: silktosilkclearance=0
SilkToSolderMaskClearance "Silk to Solder Mask Opening" [All] p1: minsilkscreentomaskgap=0 clearancetoexposedcopper=FALSE
SolderMaskExpansion [All] p1: expansion=0 istentingtop=FALSE
Width [All] p1: maxlimit=100 minlimit=3.25 preferedwidth=3.5 toplayer_minwidth=4 toplayer_prefwidth=11.5 midlayer2_prefwidth=3.3 midlayer3_prefwidth=3.3 midlayer7_prefwidth=3.3 midlayer11_prefwidth=3.3 bottomlayer_minwidth=4 bottomlayer_prefwidth=11.5 minimp=50.000000 maximp=50.000000 favimp=50.000000 checkconnectedcopper=TRUE
12 further rules are at their usual default settings.

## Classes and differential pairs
component class "Balun Test RevE2": C119 C120 C121 C122 C123 C127 C138 C148 C149 J5 J22 J27 J28 J29 J30 J31 J32 J33 T3 T4 T5 T6 T7
component class Analog_Frontend_RevE2: C94 C95 C97 C99 C105 C106 C107 C108 C118 FB1 J4 J21 J26 L13 R3 R4 R6 R7 R179 R180 R181 R182 R183 R184 R185 R186 R187 R188 R189 R193 R194 R195 R196 R197 U16
component class USB_RevE2: C76 C77 C78 C79 C80 C81 C82 C83 C84 C85 C86 C87 C88 C89 J20 L14 L15 R153 R155 R156 R157 R160 R162 R163 R165 R166 R167 R168 R169 R170 U17 U18 Y1
component class Misc_RevE2: FID1 FID2 FID3 FID4 FID5 FID6 H1 H2 H3 H4 H5 H6 H7 H8 LBL1 Logo1 Logo2 Logo3 Logo4 ZZ1 ZZ2 ZZ3 ZZ4
component class Clocks3_RevE2: C324 C325 C326 C327 C328 C329 C330 C331 C332 C333 C334 C335 C336 C337 C338 C339 C340 C341 C342 C343 C344 C345 C346 C347 L33 L34 L35 R70 R252 R253 R258 R259 R262 R263 R264 R265 U52
component class Clocks2_RevE2: C96 C310 C311 C312 C313 C314 C315 C316 C317 C318 C319 C320 C321 C322 C323 C505 C506 C507 C508 J13 J17 L31 L32 R239 R240 R241 R242 R243 R244 R245 R246 R247 R248 R249 R250 R251 R277 R278 R279 U31 U50 U51
component class ADC_Input_RevE2: C74 C75 C90 C91 C93 J6 J7 J8 R11 R12 R13 R15 R22 R23 T2
component class ADC_Power_RevE2: C124 C125 C156 C157 C158 C159 C160 C161 C162 C163 C167 C168 C169 C170 C171 C172 C173 C174 C175 C176 C178 C179 C180 C181 C182 C183
component class FMC_RevE2: C92 C126 C290 J1 J24 J25 R103 R104 R105 R107 R215 R217 R218 R220 R254 R255 R807 R808 U5 U20 U59
component class ADC_RevE2: C2 C3 C4 C5 C13 C14 C15 C16 C17 C18 C19 C20 C21 C22 C23 C24 C25 C26 C27 C28 C29 C30 C31 C32 C33 C34 C35 C36 C37 C38 C39 C40 C41 C42 C43 C44 C45 C46 C52 C60 C61 C73 C98 C285 C306 C415 C416 C417 D1 J9 J10 J11 J16 Q1 R1 R2 R20 R21 R24 R25 R26 R29 R171 R172 R174 T1 TP1 TP2 TP3 TP4 U1 U4
component class Clocks_RevE2: C1 C6 C47 C48 C49 C50 C51 C53 C54 C55 C56 C57 C58 C59 C64 C65 J2 L3 L4 L5 L6 L7 L8 L9 L10 L11 L12 R30 R31 R32 R34 R37 R38 R39 R40 R41 R42 R43 R44 R45 R46 R47 R48 R49 R50 R51 R52 R53 R55 R56 R57 R58 R61 R62 R63 R64 R65 R66 R226 R227 R238 R256 R359 R360 R451 U6 U49
component class Power2_RevE2: C8 C9 C10 C11 C12 C62 C63 C66 C67 C68 C69 C70 C71 C72 C100 C101 C102 C103 C104 C112 C113 C114 C115 C116 C117 C128 C129 C130 C131 C132 C133 C134 C135 C136 C137 C139 C140 C141 C142 C143 C144 C145 C146 C147 C164 C165 C184 C185 C186 C187 C188 C189 C190 C192 C193 C194 C195 C199 C200 C201 C202 C203 C243 C244 C245 FB2 FB4 FB8 FB9 FB10 FB11 J3 L1 L2 L27 R5 R92 R93 R94 R95 R96 R97 R98 R99 R100 R101 R102 R110 R111 R112 R113 R114 R115 R116 R117 R118 R119 R120 R121 R122 R123 R124 R125 R126 R198 R199 R228 R229 R230 R231 R232 R280 R888 R950 TP5 TP6 TP7 TP9 TP20 U7 U8 U9 U10 U19 U43
component class Power1_RevE2: C7 C109 C110 C111 C204 C205 C206 C207 C208 C209 C210 C211 C212 C213 C214 C215 C216 C217 C218 C220 C221 C222 C223 C224 C225 C226 C227 C228 C229 C230 C231 C235 C236 C237 C241 C242 C307 C308 C309 C359 C360 D6 D7 FB3 FB5 FB6 FB7 J14 L17 Q2 R127 R128 R129 R130 R131 R132 R133 R134 R135 R136 R137 R138 R139 R140 R141 R142 R143 R144 R145 R146 R175 R233 R801 TP10 TP11 TP16 TP21 U11 U12 U21 U22 U23 U57 U58 Y3
component class GPIO_RevE2: C287 C288 C405 D2 D3 D4 D5 J12 J18 J23 R27 R28 R33 R35 R36 R60 R67 R68 R69 R71 R82 R83 R84 R87 R89 R90 R91 R108 R109 R147 R152 R158 R159 R161 R164 R176 R177 R216 R219 TP8 TP12 TP13 TP14 TP15 U36
component class GPIO2_RevE2: C421 C422 C423 C424 C425 C426 C427 C428 C429 C430 C431 C432 C433 J15 J19 R54 R59 R72 R73 R74 R75 R76 R77 R78 R79 R80 R81 R85 R86 R88 R106 R148 R149 R150 R151 R178 R207 R305 R750 R804 R805 R851 R852 U13 U14 U15 U30 U32 U33 U34 U41 U42
differential pair NewDifferentialPair38: +INB_ADC_P -INB_ADC_N
differential pair NewDifferentialPair37: +INA_ADC_P -INA_ADC_N
differential pair FPGA_GBTCLK1_FMC: +FPGA_GBTCLK1_FMC_P -FPGA_GBTCLK1_FMC_N
differential pair DB7_ADC: +DB7_ADC_P -DB7_ADC_N
differential pair DB6_ADC: +DB6_ADC_P -DB6_ADC_N
differential pair DB5_ADC: +DB5_ADC_P -DB5_ADC_N
differential pair DB4_ADC: +DB4_ADC_P -DB4_ADC_N
differential pair DB3_ADC: +DB3_ADC_P -DB3_ADC_N
differential pair DB2_ADC: +DB2_ADC_P -DB2_ADC_N
differential pair DB1_ADC: +DB1_ADC_P -DB1_ADC_N
differential pair DB0_ADC: +DB0_ADC_P -DB0_ADC_N
differential pair DA7_ADC: +DA7_ADC_P -DA7_ADC_N
differential pair DA6_ADC: +DA6_ADC_P -DA6_ADC_N
differential pair DA5_ADC: +DA5_ADC_P -DA5_ADC_N
differential pair DA4_ADC: +DA4_ADC_P -DA4_ADC_N
differential pair DA3_ADC: +DA3_ADC_P -DA3_ADC_N
differential pair DA2_ADC: +DA2_ADC_P -DA2_ADC_N
differential pair DA1_ADC: +DA1_ADC_P -DA1_ADC_N
differential pair DA0_ADC: +DA0_ADC_P -DA0_ADC_N
differential pair CLK_ADC: +CLK_ADC_P -CLK_ADC_N
differential pair DA0_FMC: +DA0_FMC_P -DA0_FMC_N
differential pair DA1_FMC: +DA1_FMC_P -DA1_FMC_N
differential pair DA2_FMC: +DA2_FMC_P -DA2_FMC_N
differential pair DA3_FMC: +DA3_FMC_P -DA3_FMC_N
differential pair DA4_FMC: +DA4_FMC_P -DA4_FMC_N
differential pair DA5_FMC: +DA5_FMC_P -DA5_FMC_N
differential pair DA6_FMC: +DA6_FMC_P -DA6_FMC_N
differential pair DA7_FMC: +DA7_FMC_P -DA7_FMC_N
differential pair DB0_FMC: +DB0_FMC_P -DB0_FMC_N
differential pair DB1_FMC: +DB1_FMC_P -DB1_FMC_N
differential pair DB2_FMC: +DB2_FMC_P -DB2_FMC_N
differential pair DB3_FMC: +DB3_FMC_P -DB3_FMC_N
differential pair DB4_FMC: +DB4_FMC_P -DB4_FMC_N
differential pair DB5_FMC: +DB5_FMC_P -DB5_FMC_N
differential pair DB6_FMC: +DB6_FMC_P -DB6_FMC_N
differential pair DB7_FMC: +DB7_FMC_P -DB7_FMC_N
differential pair SYSREF_ADC: +SYSREF_ADC_P -SYSREF_ADC_N
differential pair FGPA_GBTCLK5_FMC: +FGPA_GBTCLK5_FMC_P -FGPA_GBTCLK5_FMC_N
differential pair FPGA_CLKB_FMC: +FPGA_CLKB_FMC_P -FPGA_CLKB_FMC_N
differential pair FPGA_GBTCLK0_FMC: +FPGA_GBTCLK0_FMC_P -FPGA_GBTCLK0_FMC_N
differential pair FPGA_SYSREF_FMC: +FPGA_SYSREF_FMC_P -FPGA_SYSREF_FMC_N
differential pair SYSREF_ADC_LMK: +SYSREF_ADC_LMK_P -SYSREF_ADC_LMK_N
differential pair FPGA_CLKA_FMC: +FPGA_CLKA_FMC_P -FPGA_CLKA_FMC_N

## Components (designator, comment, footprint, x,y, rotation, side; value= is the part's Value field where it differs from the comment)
C1 "0201BB104KW160" 0201_033L 6935,2330 r180 bottom value=0.1uF
C2 "0201BB104KW160" 0201_033L 6081.05,1352.98 r270 top value=0.1uF
C3 "0201BB104KW160" 0201_033L 6081.05,1397.02 r90 top value=0.1uF
C4 "C0603C0G1E101J030BA" 0201_033 5259.25,555.47 r90 bottom value=100pF
C5 "C0603C0G1E101J030BA" 0201_033 5224.25,555.47 r90 bottom value=100pF
C6 "0201BB104KW160" 0201_033L 6935,2360 r180 bottom value=0.1uF
C7 "GRM32ER71A476KE15L" 1210_270 3340,2245 r270 top value=47uF
C8 "GRM32ER71A476KE15L" 1210_270 2785,1800 r90 top value=47uF
C9 "GRM32ER71A476KE15L" 1210_270 2935,1562.09 r270 top value=47uF
C10 "GRM32ER71A476KE15L" 1210_270 2780,895 r270 top value=47uF
C11 "GRM32ER71A476KE15L" 1210_270 2930,897.09 r270 top value=47uF
C12 "GRM32ER71A476KE15L" 1210_270 2780,1135 r90 top value=47uF
C13 "0201BB104KW160" 0201_033L 6540,1422.01 r180 top value=0.1uF
C14 "0201BB104KW160" 0201_033L 6540,1391.01 r180 top value=0.1uF
C15 "0201BB104KW160" 0201_033L 6540,1485 r180 top locked value=0.1uF
C16 "0201BB104KW160" 0201_033L 6540,1454 r180 top value=0.1uF
C17 "0201BB104KW160" 0201_033L 6410.47,1615 r270 top value=0.1uF
C18 "0201BB104KW160" 0201_033L 6441.47,1615 r270 top value=0.1uF
C19 "0201BB104KW160" 0201_033L 6347.48,1615 r270 top value=0.1uF
C20 "0201BB104KW160" 0201_033L 6378.48,1615 r270 top value=0.1uF
C21 "0201BB104KW160" 0201_033L 6455,1426 r180 bottom value=0.1uF
C22 "0201BB104KW160" 0201_033L 6455,1394 r180 bottom value=0.1uF
C23 "0201BB104KW160" 0201_033L 6455,1486 r180 bottom value=0.1uF
C24 "0201BB104KW160" 0201_033L 6455,1454 r180 bottom value=0.1uF
C25 "0201BB104KW160" 0201_033L 6409.24,1527.76 r270 bottom value=0.1uF
C26 "0201BB104KW160" 0201_033L 6441.24,1527.76 r270 bottom value=0.1uF
C27 "0201BB104KW160" 0201_033L 6347.74,1527.76 r270 bottom value=0.1uF
C28 "0201BB104KW160" 0201_033L 6379.74,1527.76 r270 bottom value=0.1uF
C29 "0201BB104KW160" 0201_033L 6540,1328.02 r180 top value=0.1uF
C30 "0201BB104KW160" 0201_033L 6540,1359.02 r180 top value=0.1uF
C31 "0201BB104KW160" 0201_033L 6540,1265.02 r180 top value=0.1uF
C32 "0201BB104KW160" 0201_033L 6540,1296.02 r180 top value=0.1uF
C33 "0201BB104KW160" 0201_033L 6410.5,1135 r90 top value=0.1uF
C34 "0201BB104KW160" 0201_033L 6441.5,1135 r90 top value=0.1uF
C35 "0201BB104KW160" 0201_033L 6347.5,1135 r90 top value=0.1uF
C36 "0201BB104KW160" 0201_033L 6378.5,1135 r90 top value=0.1uF
C37 "0201BB104KW160" 0201_033L 6455,1329 r180 bottom value=0.1uF
C38 "0201BB104KW160" 0201_033L 6455,1361 r180 bottom value=0.1uF
C39 "0201BB104KW160" 0201_033L 6455,1264 r180 bottom value=0.1uF
C40 "0201BB104KW160" 0201_033L 6455,1296 r180 bottom value=0.1uF
C41 "0201BB104KW160" 0201_033L 6409,1220 r90 bottom value=0.1uF
C42 "0201BB104KW160" 0201_033L 6441,1220 r90 bottom value=0.1uF
C43 "0201BB104KW160" 0201_033L 6349,1220 r90 bottom value=0.1uF
C44 "0201BB104KW160" 0201_033L 6381,1220 r90 bottom value=0.1uF
C45 "0201BB104KW160" 0201_033L 5961,1359.98 r180 top value=0.1uF
C46 "0201BB104KW160" 0201_033L 5961,1389 r180 top value=0.1uF
C47 "GRM155R70J105KA12D" 0402L 7010,2250 r0 top value=1uF
C48 "GRM033Z71C104KE14D" 0201L 7370,2400 r90 bottom value=0.1uF
C49 "0201BB104KW160" 0201_033L 6936.02,2268 r180 bottom value=0.1uF
C50 "0201BB104KW160" 0201_033L 6936.02,2293 r180 bottom value=0.1uF
C51 "GRM033Z71C104KE14D" 0201 8070,2655 r0 top value=0.1uF
C52 "0201BB104KW160" 0201_033L 5837.08,1185.05 r180 top value=0.1uF
C53 "GRM155R70J105KA12D" 0402L 7375,2185 r180 top value=1uF
C54 "GRM155R70J105KA12D" 0402L 7260,2150 r135 bottom value=1uF
C55 "GRM155R70J105KA12D" 0402L 7125,2250 r270 top value=1uF
C56 "GRM155R70J105KA12D" 0402L 7025,2645 r270 bottom value=1uF
C57 "GRM155R70J105KA12D" 0402L 7375,2535 r180 top value=1uF
C58 "GRM155R70J105KA12D" 0402L 6910,2540 r90 bottom value=1uF
C59 "GRM033Z71C104KE14D" 0201L 6880,2530 r90 bottom value=0.1uF
C60 "0201BB104KW160" 0201_033L 5848.08,1196.05 r90 top value=0.1uF
C61 "0201BB104KW160" 0201_033L 5849.08,1144.05 r270 top value=0.1uF
C62 "GRM188Z71A106MA73D" 0603 3685,1005.43 r90 top value=10uF
C63 "GRM188Z71A106MA73D" 0603 3825,1005.43 r90 top value=10uF
C64 "GRM188Z71A106MA73D" 0603L 7305,2350 r180 top value=10uF
C65 "GRM033Z71C104KE14D" 0201L 7385,2330 r0 bottom value=0.1uF
C66 "GRM188Z71A106MA73D" 0603 3755,1005.43 r90 top value=10uF
C67 "GRM188R71E474KA12D" 0603 2080,340 r90 top value=0.47uF
C68 "C3216X7R1V106K160AC" 1206_180 1950,150 r0 top value=10uF
C69 "C3216X7R1V106K160AC" 1206_180 1805,595 r180 top value=10uF
C70 "C3216X7R1V106K160AC" 1206_180 1995,595 r0 top value=10uF
C71 "C1608X7R1E104K080AA" 0603 1840,515 r180 top value=0.1uF
C72 "C1608X7R1E104K080AA" 0603 1975,515 r0 top value=0.1uF
C73 "0201BB104KW160" 0201_033L 6013,1352.93 r90 top value=0.1uF
C74 "0201BB104KW160" 0201_033 6208.01,915.02 r180 top value=0.1uF
C75 "0201BB104KW160" 0201_033 6187,257.05 r270 top value=0.1uF
C76 "GRM033Z71C104KE14D" 0201L 920.88,814.34 r0 bottom value=0.1uF
C77 "GRM033Z71C104KE14D" 0201L 670.09,661.98 r270 bottom value=0.1uF
C78 "GRM033Z71C104KE14D" 0201L 886.63,947.02 r90 bottom value=0.1uF
C79 "GRM033Z71C104KE14D" 0201L 768.52,947.02 r90 bottom value=0.1uF
C80 "C1608X5R1E335K080AC" 0603 956.5,988.5 r0 bottom value=3.3uF
C81 "GRM033Z71C104KE14D" 0201L 920.88,715.92 r0 bottom value=0.1uF
C82 "GRM033Z71C104KE14D" 0201L 636,912.5 r180 bottom value=0.1uF
C83 "GRM188Z71C475KE21D" 0603 528.5,772.5 r180 bottom value=4.7uF
C84 "GRM033Z71C104KE14D" 0201L 635.98,775 r180 bottom value=0.1uF
C85 "GRM188Z71C475KE21D" 0603 519,853.5 r180 bottom value=4.7uF
C86 "GRM033Z71C104KE14D" 0201L 636,853.5 r180 bottom value=0.1uF
C87 "C1005C0G1H180J050BA" 0402L 540,977 r180 bottom value=18pF
C88 "C1005C0G1H180J050BA" 0402L 416,976 r0 bottom value=18pF
C89 "GRM033Z71C104KE14D" 0201L 907.02,1138 r0 bottom value=0.1uF
C90 "0201BB104KW160" 0201_033 6221,903.03 r270 top value=0.1uF
C91 "0201BB104KW160" 0201_033 6253,903.03 r270 top value=0.1uF
C92 "GRM033Z71C104KE14D" 0201L 8550,100 r180 top value=0.1uF
C93 "0201BB104KW160" 0201_033 6265.97,916 r0 top value=0.1uF
C94 "GRM033Z71C104KE14D" 0201 6126,1848.01 r270 top value=0.1uF
C95 "GRM033Z71C104KE14D" 0201 6146,1848.01 r270 top value=0.1uF
C96 "GRM033Z71C104KE14D" 0201L 4575,1735 r0 bottom value=0.1uF
C97 "GRM188Z71A106MA73D" 0603 6076,1891.98 r90 top value=10uF
C98 "0201BB104KW160" 0201_033L 6013,1397.02 r270 top value=0.1uF
C99 "0201BB104KW160" 0201_033 6248.92,1751 r90 top value=0.1uF
C100 "C1608X7R1E104K080AA" 0603 1950,235 r0 top value=0.1uF
C101 "GRM32ER71A476KE15L" 1210_270 2775,490 r90 top value=47uF
C102 "GRM32ER71A476KE15L" 1210_270 2775,250 r270 top value=47uF
C103 "GRM32ER71A476KE15L" 1210_270 2925,490 r90 top value=47uF
C104 "GRM32ER71A476KE15L" 1210_270 2925,252.09 r270 top value=47uF
C105 "0201BB104KW160" 0201_033 6224.92,1751 r90 top value=0.1uF
C106 "GRM0335C1HR30BA01D" CAPC0603X33X15LL03T05 6216.21,2015.22 r0 top value=0.3pF
C107 "0201BB104KW160" 0201_033 6227.23,1944.5 r90 top value=0.1uF
C108 "0201BB104KW160" 0201_033 6248.82,1944.5 r90 top value=0.1uF
C109 "GRM188Z71A106MA73D" 0603 3690,1821.93 r270 top value=10uF
C110 "GRM188Z71A106MA73D" 0603 3760,1821.93 r270 top value=10uF
C111 "GRM188Z71A106MA73D" 0603 3830,1821.93 r270 top value=10uF
C112 "GRM188Z71A106MA73D" 0603 2169.01,2428.02 r90 bottom value=10uF
C113 "GRM188Z71A106MA73D" 0603 2781.68,2311.53 r270 bottom value=10uF
C114 "C1608X7R1E104K080AA" 0603 2849.01,2311.53 r270 bottom value=0.1uF
C115 "GRM033Z71C104KE14D" 0201 1737.99,295.75 r0 top value=0.1uF
C116 "GRM188Z71C475KE21D" 0603 1775,240 r0 top value=4.7uF
C117 "GCM0335C1E220JD03D" 0201_033 1815,325 r180 bottom value=22pF
C118 "GRM0335C1HR30BA01D" CAPC0603X33X15LL03T05 6216.21,1974.89 r0 top value=0.3pF
C119 "0201BB104KW160" 0201_033 9524.51,1188.48 r180 top value=0.1uF
C120 "0201BB104KW160" 0201_033 10130.06,1242.67 r225 top value=0.1uF
C121 "0201BB104KW160" 0201_033 10130.06,1034.3 r135 top value=0.1uF
C122 "0201BB104KW160" 0201_033 9725,1693.99 r270 top value=0.1uF
C123 "0201BB104KW160" 0201_033 9532.93,2400.04 r135 top value=0.1uF
C124 "GRM033Z71C104KE14D" 0201L 6306,1317 r45 bottom value=0.1uF
C125 "GRM033Z71C104KE14D" 0201L 6307,1365 r315 bottom value=0.1uF
C126 "GRM033Z71C104KE14D" 0201L 4265,730 r90 bottom value=0.1uF
C127 "0201BB104KW160" 0201_033 10017.07,2400.04 r45 top value=0.1uF
C128 "C3216X7R1V106K160AC" 1206_180 1815,1905 r180 top value=10uF
C129 "GRM188R71E474KA12D" 0603 2090,1650 r90 top value=0.47uF
C130 "C3216X7R1V106K160AC" 1206_180 2005,1905 r0 top value=10uF
C131 "C3216X7R1V106K160AC" 1206_180 1960,1460 r0 top value=10uF
C132 "C1608X7R1E104K080AA" 0603 1850,1825 r180 top value=0.1uF
C133 "C1608X7R1E104K080AA" 0603 1960,1545 r0 top value=0.1uF
C134 "C1608X7R1E104K080AA" 0603 1985,1825 r0 top value=0.1uF
C135 "GRM32ER71A476KE15L" 1210_270 2785,1560 r270 top value=47uF
C136 "GRM033Z71C104KE14D" 0201 1747.99,1605.75 r0 top value=0.1uF
C137 "GRM188Z71C475KE21D" 0603 1785,1550 r0 top value=4.7uF
C138 "0201BB104KW160" 0201_033 10119.49,440 r0 top value=0.1uF
C139 "GRM188Z71A106MA73D" 0603 3690,1670.43 r90 top value=10uF
C140 "GRM188Z71A106MA73D" 0603 3760,1670.43 r90 top value=10uF
C141 "GRM188Z71A106MA73D" 0603 3830,1670.43 r90 top value=10uF
C142 "GRM188Z71A106MA73D" 0603 3095,1885 r90 top value=10uF
C143 "GCM0335C1E220JD03D" 0201_033 1825,1635 r180 bottom value=22pF
C144 "GRM033R71A103KA01D" 0201 3090,1800 r180 top value=0.01uF
C145 "GRM188Z71A106MA73D" 0603 3360,530 r90 top value=10uF
C146 "GRM188Z71A106MA73D" 0603 3290,530 r90 top value=10uF
C147 "GRM188Z71A106MA73D" 0603 3220,530 r90 top value=10uF
C148 "0201BB104KW160" 0201_033 9513.94,385.81 r45 top value=0.1uF
C149 "0201BB104KW160" 0201_033 9513.94,594.19 r315 top value=0.1uF
C156 "GRM033Z71C104KE14D" 0201L 6379,1470 r90 bottom value=0.1uF
C157 "GRM033Z71C104KE14D" 0201L 6410,1470 r90 bottom value=0.1uF
C158 "GRM033Z71C104KE14D" 0201L 6379,1407 r90 bottom value=0.1uF
C159 "GRM033Z71C104KE14D" 0201L 6410,1407 r90 bottom value=0.1uF
C160 "GRM033Z71C104KE14D" 0201L 6379,1344 r270 bottom value=0.1uF
C161 "GRM033Z71C104KE14D" 0201L 6410,1344 r270 bottom value=0.1uF
C162 "GRM033Z71C104KE14D" 0201L 6410,1281 r270 bottom value=0.1uF
C163 "GRM033Z71C104KE14D" 0201L 6379,1281 r270 bottom value=0.1uF
C164 "GRM033R71A103KA01D" 0201 3385,1825.75 r180 top value=0.01uF
C165 "GRM188R71E474KA12D" 0603 2085,985 r90 top value=0.47uF
C167 "GRM033Z71C104KE14D" 0201L 6253,1249 r90 bottom value=0.1uF
C168 "GRM033Z71C104KE14D" 0201L 6268,1296 r180 bottom value=0.1uF
C169 "GRM033Z71C104KE14D" 0201L 6268,1391 r180 bottom value=0.1uF
C170 "GRM033Z71C104KE14D" 0201L 6266,1328 r180 bottom value=0.1uF
C171 "GRM033Z71C104KE14D" 0201L 6266,1360 r180 bottom value=0.1uF
C172 "GRM033Z71C104KE14D" 0201L 6268,1423 r180 bottom value=0.1uF
C173 "GRM033Z71C104KE14D" 0201L 6268,1454 r180 bottom value=0.1uF
C174 "GRM033Z71C104KE14D" 0201L 6252,1501 r270 bottom value=0.1uF
C175 "GRM033Z71C104KE14D" 0201L 6143,1454 r0 bottom value=0.1uF
C176 "GRM033Z71C104KE14D" 0201L 6143,1296 r0 bottom value=0.1uF
C178 "GRM033Z71C104KE14D" 0201L 6221,1249 r90 bottom value=0.1uF
C179 "GRM033Z71C104KE14D" 0201L 6221,1501 r270 bottom value=0.1uF
C180 "GRM033Z71C104KE14D" 0201L 6158,1343 r270 bottom value=0.1uF
C181 "GRM033Z71C104KE14D" 0201L 6206,1359 r0 bottom value=0.1uF
C182 "GRM033Z71C104KE14D" 0201L 6206,1391 r0 bottom value=0.1uF
C183 "GRM033Z71C104KE14D" 0201L 6158,1406 r90 bottom value=0.1uF
C184 "C3216X7R1V106K160AC" 1206_180 1810,1240 r180 top value=10uF
C185 "C3216X7R1V106K160AC" 1206_180 2000,1240 r0 top value=10uF
C186 "C3216X7R1V106K160AC" 1206_180 1955,795 r0 top value=10uF
C187 "C1608X7R1E104K080AA" 0603 1845,1160 r180 top value=0.1uF
C188 "C1608X7R1E104K080AA" 0603 1955,880 r0 top value=0.1uF
C189 "C1608X7R1E104K080AA" 0603 1980,1160 r0 top value=0.1uF
C190 "GRM32ER71A476KE15L" 1210_270 2930,1135 r90 top value=47uF
C192 "GRM033Z71C104KE14D" 0201 1742.99,940.75 r0 top value=0.1uF
C193 "GRM188Z71C475KE21D" 0603 1780,885 r0 top value=4.7uF
C194 "GCM0335C1E220JD03D" 0201_033 1825,1010 r180 bottom value=22pF
C195 "GRM188Z71A106MA73D" 0603 3090,1220 r90 top value=10uF
C199 "GRM033R71A103KA01D" 0201 3085,1135 r180 top value=0.01uF
C200 "GRM033R71A103KA01D" 0201 3380,1160.75 r180 top value=0.01uF
C201 "GRM188Z71A106MA73D" 0603 3688.54,1240 r90 top value=10uF
C202 "GRM188Z71A106MA73D" 0603 3758.54,1240 r90 top value=10uF
C203 "GRM188Z71A106MA73D" 0603 3828.54,1240 r90 top value=10uF
C204 "GRM033Z71C104KE14D" 0201 1209,890 r0 top value=0.1uF
C205 "C1608X7R1E104K080AA" 0603 1366,1213 r0 top value=0.1uF
C206 "GRM188R71A105KA61D" 0603 1366,1133 r0 top value=1uF
C207 "GRM033Z71C104KE14D" 0201 1251,1043 r0 top value=0.1uF
C208 "GRM188R71E474KA12D" 0603 2090,2300 r90 top value=0.47uF
C209 "C3216X7R1V106K160AC" 1206_180 1815,2555 r180 top value=10uF
C210 "C3216X7R1V106K160AC" 1206_180 2005,2555 r0 top value=10uF
C211 "C3216X7R1V106K160AC" 1206_180 1960,2110 r0 top value=10uF
C212 "C1608X7R1E104K080AA" 0603 1985,2475 r0 top value=0.1uF
C213 "C1608X7R1E104K080AA" 0603 1960,2195 r0 top value=0.1uF
C214 "C1608X7R1E104K080AA" 0603 1850,2475 r180 top value=0.1uF
C215 "GRM32ER71A476KE15L" 1210_270 2785,2450 r90 top value=47uF
C216 "GRM32ER71A476KE15L" 1210_270 2935,2212.09 r270 top value=47uF
C217 "GRM32ER71A476KE15L" 1210_270 2785,2210 r270 top value=47uF
C218 "GRM32ER71A476KE15L" 1210_270 2935,2450 r90 top value=47uF
C220 "GRM033Z71C104KE14D" 0201 1747.99,2255.75 r0 top value=0.1uF
C221 "GRM188Z71C475KE21D" 0603 1785,2200 r0 top value=4.7uF
C222 "GCM0335C1E220JD03D" 0201_033 1827.01,2285 r180 bottom value=22pF
C223 "GRM188Z71A106MA73D" 0603 3095,2535 r90 top value=10uF
C224 "GRM188Z71A106MA73D" 0603 3831.46,2540 r270 top value=10uF
C225 "GRM188Z71A106MA73D" 0603 3761.46,2540 r270 top value=10uF
C226 "GRM188Z71A106MA73D" 0603 3691.46,2540 r270 top value=10uF
C227 "GRM033R71A103KA01D" 0201 3090,2450 r180 top value=0.01uF
C228 "GRM033R71A103KA01D" 0201 3385,2475.75 r180 top value=0.01uF
C229 "GRM188Z71A106MA73D" 0603 3830,2314.57 r270 top value=10uF
C230 "GRM188Z71A106MA73D" 0603 3760,2314.57 r270 top value=10uF
C231 "GRM188Z71A106MA73D" 0603 3690,2314.57 r270 top value=10uF
C235 "C0805C105K5RACTU" 0805_HV 840,2175 r90 top value=1uF
C236 "C0805C105K5RACTU" 0805_HV 1297.56,2211 r90 top value=1uF
C237 "C0805C105K5RACTU" 0805_HV 1392.56,2211 r90 top value=1uF
C241 "GRM033R71E102KA01D" 0201_033 1051.62,2281 r180 top value=1000pF
C242 "GRM033R71E102KA01D" 0201_033 1051.62,2319 r180 top value=1000pF
C243 "GRM32ER71A476KE15L" 1210_270 2935,1800 r90 top value=47uF
C244 "GRM32ER71A476KE15L" 1210_270 3335,1585 r270 top value=47uF
C245 "GRM32ER71A476KE15L" 1210_270 3335,925 r270 top value=47uF
C285 "0201BB104KW160" 0201_033L 5227.98,1216 r180 bottom value=0.1uF
C287 "GRM033Z71C104KE14D" 0201 4882.99,169.25 r180 bottom value=0.1uF
C288 "GRM033Z71C104KE14D" 0201 4787.99,182.56 r90 bottom value=0.1uF
C290 "GRM033Z71C104KE14D" 0201L 4165,730 r90 bottom value=0.1uF
C306 "0201BB104KW160" 0201_033L 5838.1,1155.05 r180 top value=0.1uF
C307 "GRM188Z71A106MA73D" 0603 3830,2186.5 r90 top value=10uF
C308 "GRM188Z71A106MA73D" 0603 3760,2186.5 r90 top value=10uF
C309 "GRM188Z71A106MA73D" 0603 3690,2186.5 r90 top value=10uF
C310 "GRM033R71A103KA01D" 0201L 4755,1730 r90 top value=0.01uF
C311 "GRM033R71A103KA01D" 0201L 4815,1730 r90 top value=0.01uF
C312 "GRM033R71A103KA01D" 0201L 4917.09,1777.09 r0 bottom value=0.01uF
C313 "GRM033R71A103KA01D" 0201L 4757.09,1957.09 r90 bottom value=0.01uF
C314 "GRM033R71A103KA01D" 0201L 4815,1960 r90 bottom value=0.01uF
C315 "GRM155R70J105KA12D" 0402L 4742.09,2027.09 r0 bottom value=1uF
C316 "GRM155R70J105KA12D" 0402L 4570,1705 r0 bottom value=1uF
C317 "GRM033R71A103KA01D" 0201L 4917.09,1807.09 r0 bottom value=0.01uF
C318 "GRM033R71A103KA01D" 0201L 4635,1775 r90 bottom value=0.01uF
C319 "0201BB104KW160" 0201_033L 4622.09,1842.09 r180 bottom value=0.1uF
C320 "0201BB104KW160" 0201_033L 4622.09,1872.09 r180 bottom value=0.1uF
C321 "0201BB104KW160" 0201_033L 4917.09,1837.09 r0 bottom value=0.1uF
C322 "0201BB104KW160" 0201_033L 4917.09,1867.09 r0 bottom value=0.1uF
C323 "GRM033R71A103KA01D" 0201L 4970,2000 r270 bottom value=0.01uF
C324 "C0603C0G1E101J030BA" 0201_033 5855.21,1374.29 r0 top value=100pF
C325 "GRM033Z71C104KE14D" 0201L 5757.21,1327.79 r0 bottom value=0.1uF
C326 "GRM155R70J105KA12D" 0402L 5726.21,1443.79 r180 bottom value=1uF
C327 "GRM188Z71A106MA73D" 0603 5508.86,1443.22 r180 bottom value=10uF
C328 "GRM188Z71A106MA73D" 0603 5523.21,1354.79 r270 bottom value=10uF
C329 "GRM033Z71C104KE14D" 0201L 5566,1544 r90 bottom value=0.1uF
C330 "GRM033Z71C104KE14D" 0201L 5727,1469 r0 bottom value=0.1uF
C331 "GRM155R70J105KA12D" 0402L 5604.21,1326.79 r90 bottom value=1uF
C332 "GRM155R70J105KA12D" 0402L 5488.21,1295.79 r180 top value=1uF
C333 "C0603C0G1E101J030BA" 0201_033 5682.21,1192.79 r270 top value=100pF
C334 "GRM155R70J105KA12D" 0402L 5450.58,1416.79 r180 top value=1uF
C335 "GRM155R70J105KA12D" 0402L 5594.21,1536.79 r270 bottom value=1uF
C336 "GRM033R71C182KA88D" 0201 5646.2,1597.79 r0 top value=1500pF
C337 "GRM155R71C563KA88D" 0402L 5653.21,1712.79 r0 top value=0.33uF
C338 "CGA1A2X7R1E152K030BA" 0201_033 5646.2,1676.79 r0 top value=2200pF
C339 "GRM155R70J105KA12D" 0402L 5450.83,1327.79 r0 top value=1uF
C340 "GRM188Z71A106MA73D" 0603 5591.21,1641.29 r270 top value=10uF
C341 "GRM155R70J105KA12D" 0402L 5550.21,1621.48 r270 top value=1uF
C342 "GRM188Z71A106MA73D" 0603 5776.21,1559.29 r270 top value=10uF
C343 "GRM188Z71A106MA73D" 0603 5438.71,1482.79 r0 top value=10uF
C344 "GRM155R70J105KA12D" 0402L 5791.21,1466.79 r180 top value=1uF
C345 "GRM188Z71A106MA73D" 0603 5698.21,1641.29 r270 top value=10uF
C346 "0201BB104KW160" 0201_033L 5471.23,1385.79 r180 top value=0.1uF
C347 "0201BB104KW160" 0201_033L 5471.23,1363.79 r180 top value=0.1uF
C359 "GRM033Z71C104KE14D" 0201 1349,305 r90 top value=0.1uF
C360 "GRM033Z71C104KE14D" 0201 1318.01,393 r180 top value=0.1uF
C405 "GRM033Z71C104KE14D" 0201 4828.46,574.57 r180 bottom value=0.1uF
C415 "C0603C0G1E101J030BA" 0201_033 5123.98,583.19 r180 bottom value=100pF
C416 "C0603C0G1E101J030BA" 0201_033 5125,620 r180 bottom value=100pF
C417 "0201BB104KW160" 0201_033L 5135,540 r180 bottom value=0.1uF
C421 "0201BB104KW160" 0201_033L 7265,415 r270 bottom value=0.1uF
C422 "0201BB104KW160" 0201_033L 7100,385 r90 bottom value=0.1uF
C423 "0201BB104KW160" 0201_033L 7480,345 r270 bottom value=0.1uF
C424 "0201BB104KW160" 0201_033L 7640,420 r90 bottom value=0.1uF
C425 "0201BB104KW160" 0201_033L 7950,485 r270 bottom value=0.1uF
C426 "0201BB104KW160" 0201_033L 7770,455 r180 bottom value=0.1uF
C427 "0201BB104KW160" 0201_033L 7090,545 r0 bottom value=0.1uF
C428 "0201BB104KW160" 0201_033L 6915,505 r90 bottom value=0.1uF
C429 "0201BB104KW160" 0201_033L 7730,310 r315 bottom value=0.1uF
C430 "0201BB104KW160" 0201_033L 7280,285 r315 bottom value=0.1uF
C431 "0201BB104KW160" 0201_033L 8240,175 r0 bottom value=0.1uF
C432 "0201BB104KW160" 0201_033L 8240,70 r0 bottom value=0.1uF
C433 "0201BB104KW160" 0201_033L 6915,300 r270 bottom value=0.1uF
C505 "0201BB104KW160" 0201_033L 4925,1630 r180 bottom value=0.1uF
C506 "0201BB104KW160" 0201_033L 4925,1605 r180 bottom value=0.1uF
C507 "0201BB104KW160" 0201_033L 4740,1570 r90 bottom value=0.1uF
C508 "0201BB104KW160" 0201_033L 4715,1570 r90 bottom value=0.1uF
D1 "LTST-C190KRKT" LED_LTST-C190_Red 5464.25,160.47 r180 top value=Red
D2 "LTST-C170KRKT" LED_LTST-C170_Red 4785,455 r0 top value=Red
D3 "LTST-C170KRKT" LED_LTST-C170_Red 4785,360 r0 top value=Red
D4 "1N4148W-TP" SOD-123 4752.99,644.57 r180 bottom value=100V
D5 "1N4148W-TP" SOD-123 4964,330 r90 bottom value=100V
D6 "MBR130T1G" SOD-123 1239.95,2064 r180 top value=30V
D7 "SMBJ15CA" SMB-Bi 700,2170 r270 top value=15V
FB1 "BLM21SN300SN1D" FP-BLM21SN300SN1D_0805-MFG 6076,1784.43 r90 top
FB2 "BLM21SN300SN1D" FP-BLM21SN300SN1D_0805-MFG 3146,428.02 r0 top
FB3 "BLM21SN300SN1D" FP-BLM21SN300SN1D_0805-MFG 3546,1953.02 r0 top
FB4 "BLM21SN300SN1D" FP-BLM21SN300SN1D_0805-MFG 2629.01,2293.02 r0 bottom
FB5 "BLM21SN300SN1D" FP-BLM21SN300SN1D_0805-MFG 3546,2565.02 r0 top
FB6 "BLM21SN300SN1D" FP-BLM21SN300SN1D_0805-MFG 3546,2340.02 r0 top
FB7 "BLM21SN300SN1D" FP-BLM21SN300SN1D_0805-MFG 3546,2160.02 r0 top
FB8 "BLM21SN300SN1D" FP-BLM21SN300SN1D_0805-MFG 3146,318.02 r0 top
FB9 "BLM21SN300SN1D" FP-BLM21SN300SN1D_0805-MFG 3546,1583.02 r0 top
FB10 "BLM21SN300SN1D" FP-BLM21SN300SN1D_0805-MFG 3546,1128.02 r0 top
FB11 "BLM21SN300SN1D" FP-BLM21SN300SN1D_0805-MFG 3546,893.02 r0 top
FID1 "Fiducial" Fiducial10-20 560,2585 r0 top
FID2 "Fiducial" Fiducial10-20 635,135 r0 top
FID3 "Fiducial" Fiducial10-20 8901.62,2659.1 r0 top
FID4 "Fiducial" Fiducial10-20 8901.62,2659.1 r180 bottom
FID5 "Fiducial" Fiducial10-20 560,2585 r180 bottom
FID6 "Fiducial" Fiducial10-20 635,135 r180 bottom
H1 "NY PMS 440 0025 PH" "NY PMS 440 0025 PH" 4350,2550 r90 top
H2 "NY PMS 440 0025 PH" "NY PMS 440 0025 PH" 4350,200 r90 top
H3 "NY PMS 440 0025 PH" "NY PMS 440 0025 PH" 200,2550 r90 top
H4 "NY PMS 440 0025 PH" "NY PMS 440 0025 PH" 200,200 r90 top
H5 "2204" Keystone_2204 4349.99,2549.77 r180 bottom
H6 "2204" Keystone_2204 4350,200 r180 bottom
H7 "2204" Keystone_2204 200,2550 r180 bottom
H8 "2204" Keystone_2204 200,200 r180 bottom
J1 "ASP-184330-01" Samtec_ASP-184330-01 8500,1375 r180 bottom locked
J2 "SASF546-P26-X1" CONN_LTI_SASF546-P26-X1 4710,2415 r45 top
J3 "3p3V" Molex_0022284023 2532,2601 r0 top
J4 "1092-01A-6" FP-1092-01A-6_RF_JACK_18MM94_12MM7-MFG 6227.23,2918 r0 top
J5 "SASF546-P26-X1" CONN_LTI_SASF546-P26-X1 9336.52,1188.48 r270 top
J6 "SASF546-P26-X1" CONN_LTI_SASF546-P26-X1 5862,685 r135 top
J7 "1092-01A-6" FP-1092-01A-6_RF_JACK_18MM94_12MM7-MFG 6187,-173 r180 top
J8 "SASF546-P26-X1" CONN_LTI_SASF546-P26-X1 6612,685 r135 top
J9 "0853050232" Molex_0853050232 5841.12,2254.53 r180 top
J10 "SASF546-P26-X1" CONN_LTI_SASF546-P26-X1 5132,1216 r180 top
J11 "0853050232" Molex_0853050232 5558.27,1971.69 r270 top
J12 "5-146261-1" CONN_5-146261-1 4425,550 r270 top
J13 "5-146261-1" CONN_5-146261-1 3865,550 r270 top
J14 "RAPC722X" CONN_RAPC722X 1,2064.61 r180 top locked
J15 "TSW-112-07-G-D" TSW-112-07-G-D 7390,160 r0 top
J16 "61300311121" WURTH_61300311121 5285,700 r0 top
J17 "SASF546-P26-X1" CONN_LTI_SASF546-P26-X1 4310,1845 r270 top
J18 "5-146261-1" CONN_5-146261-1 4265,550 r270 top
J19 "5-146261-1" CONN_5-146261-1 1127,1443 r270 top
J20 "1734035-2" CONN_USB-Mini-B-1734035-2 208.11,788.8 r270 top
J21 "PBC03SAAN" PBC03SAAN 5949,1894 r90 top
J22 "SASF546-P26-X1" CONN_LTI_SASF546-P26-X1 10250.87,1363.48 r315 top
J23 "TSW-104-07-G-D" TSW-104-07-G-D 3703,211 r180 top
J24 "5-146261-1" CONN_5-146261-1 4130,550 r270 top
J25 "5-146261-1" CONN_5-146261-1 4000,550 r270 top
J26 "PBC03SAAN" PBC03SAAN 6708,1968 r90 top
J27 "SASF546-P26-X1" CONN_LTI_SASF546-P26-X1 10250.87,913.48 r225 top
J28 "SASF546-P26-X1" CONN_LTI_SASF546-P26-X1 9725,1506 r0 top
J29 "SASF546-P26-X1" CONN_LTI_SASF546-P26-X1 9400,2532.97 r45 top
J30 "SASF546-P26-X1" CONN_LTI_SASF546-P26-X1 10150,2532.97 r315 top
J31 "SASF546-P26-X1" CONN_LTI_SASF546-P26-X1 10307.48,440 r90 top
J32 "SASF546-P26-X1" CONN_LTI_SASF546-P26-X1 9393.13,265 r135 top
J33 "SASF546-P26-X1" CONN_LTI_SASF546-P26-X1 9393.13,715 r45 top
L1 "XAL8080-103MEB" XAL8080 2415,1695 r0 top value=10uH
L2 "XAL8080-103MEB" XAL8080 2410,1030 r0 top value=10uH
L3 "74279271" 0402L 7425,2390 r180 bottom value="120 ohm"
L4 "74279271" 0402L 7375,2185 r180 bottom value="120 ohm"
L5 "74279271" 0402L 7260,2150 r135 top value="120 ohm"
L6 "74279271" 0402L 6850,2540 r270 bottom value="120 ohm"
L7 "74279271" 0402L 6985,2190 r0 top value="120 ohm"
L8 "74279271" 0402L 6930,2405 r0 bottom value="120 ohm"
L9 "74279271" 0402L 6930,2440 r0 bottom value="120 ohm"
L10 "74279271" 0402L 6930,2485 r0 bottom value="120 ohm"
L11 "74279271" 0402L 7055,2645 r270 bottom value="120 ohm"
L12 "74279271" 0402L 7375,2570 r180 top value="120 ohm"
L13 "LQW03AW1N8C00D" FP-LQW03AW1N8C00D_0201-MFG 6227.23,1995.15 r270 top
L14 "74279271" 0402 536,711.5 r0 bottom value="120 ohm"
L15 "74279271" 0402 527.5,910.5 r0 bottom value="120 ohm"
L17 "XAL8080-103MEB" XAL8080 2415,2345 r0 top value=10uH
L27 "XAL8080-103MEB" XAL8080 2405,385 r0 top value=10uH
L31 "74279271" 0402L 4722.09,1967.09 r90 bottom value="120 ohm"
L32 "74279271" 0402L 4580,1765 r0 bottom value="120 ohm"
L33 "LQG15HS18NJ02D" IND_LQG15H 5791.21,1369.79 r180 bottom value=18nH
L34 "74279271" 0402 5745.21,1389.79 r270 bottom value="120 ohm"
L35 "LQG15HS18NJ02D" IND_LQG15H 5682.21,1256.09 r90 bottom value=18nH
LBL1 "THT-14-423-10" Label_650x200 411,1324 r180 top
Logo1 "Texas Instruments" TI_Stacked_Overlay_Small 491,1569 r0 top
Logo2 "CE Mark" CE_Mark_5mm 2563,529 r180 bottom
Logo3 "FCC disclaimer" FCC_disclaimer 1538,69 r180 bottom
Logo4 "WEEE logo" WEEE_Minimum 2265,560 r180 bottom
Q1 "MMBT3904" SOT-23 5060,595 r180 top value="40 V"
Q2 "CSD15571Q2" DQK0006C 945,2230 r90 top value=20V
R1 "ERJ-1GEF49R9C" 0201L 6038,1351.94 r90 top value=49.9
R2 "ERJ-1GEF49R9C" 0201L 6038,1396.95 r270 top value=49.9
R3 "CRCW020110K0FKED" 0201 6379.5,1899.99 r90 top value=10.0k
R4 "CRCW020110K0FKED" 0201 6379.5,1840.93 r270 top value=10.0k
R5 "RC0603FR-0735K7L" 0603 2453.51,2504 r0 bottom value=35.7k
R6 "ERJ-1GN0R00C" 0201 6227.23,2045.61 r270 top value=0
R7 "ERJ-1GE0R00C" 0201 6348,1900 r270 top value=0
R11 "RC0201FR-078R66L" 0201 6221,1146 r90 top value=8.66
R12 "RC0201FR-07140RL" 0201 6266,1116 r180 top value=140
R13 "RC0201FR-07140RL" 0201 6208,1116 r180 top value=140
R15 "RC0201FR-078R66L" 0201 6253,1146 r90 top value=8.66
R20 "CRCW02010000Z0ED" 0201 5295,590 r270 bottom value=0
R21 "CRCW02010000Z0ED" 0201 5185,590 r270 bottom value=0
R22 "RC0201FR-078R66L" 0201 6221,1086 r90 top value=8.66
R23 "RC0201FR-078R66L" 0201 6253,1086 r90 top value=8.66
R24 "RC0201FR-7D10KL" 0201 5110,295 r270 bottom value=10.0k
R25 "RC0201FR-7D10KL" 0201 5195,280 r270 bottom value=10.0k
R26 "RC0201FR-7D10KL" 0201 5245,290 r270 bottom value=10.0k
R27 "RC0201FS-7D100RL" 0201L 4496.02,510 r90 bottom value=100
R28 "RC0201FR-0747KL" 0201L 4472,510 r270 bottom value=47.0k
R29 "RC0201FR-07750RL" 0201 5480,205 r0 bottom value=750
R30 "ERJ-2RKF49R9X" 0402L 6818.62,2371.81 r225 bottom value=49.9
R31 "RC0201FR-7D10KL" 0201L 7320,2435 r180 top value=10.0k
R32 "CRCW02010000Z0ED" 0201L 6770,2385 r315 bottom value=0
R33 "RC0201FS-7D100RL" 0201L 7345,690 r180 bottom value=100
R34 "RC0201FS-7D100RL" 0201L 7200,2615 r180 bottom value=100
R35 "RC0201FS-7D1KL" 0201L 4496.02,610 r270 bottom value=1.00k
R36 "RC0201FS-7D100RL" 0201L 7495,690 r180 bottom value=100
